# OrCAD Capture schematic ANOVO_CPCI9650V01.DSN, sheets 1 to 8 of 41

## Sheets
1 -COVER PAGE: title: 01--COVER PAGE; rev: 0.1; note: CPCI 965
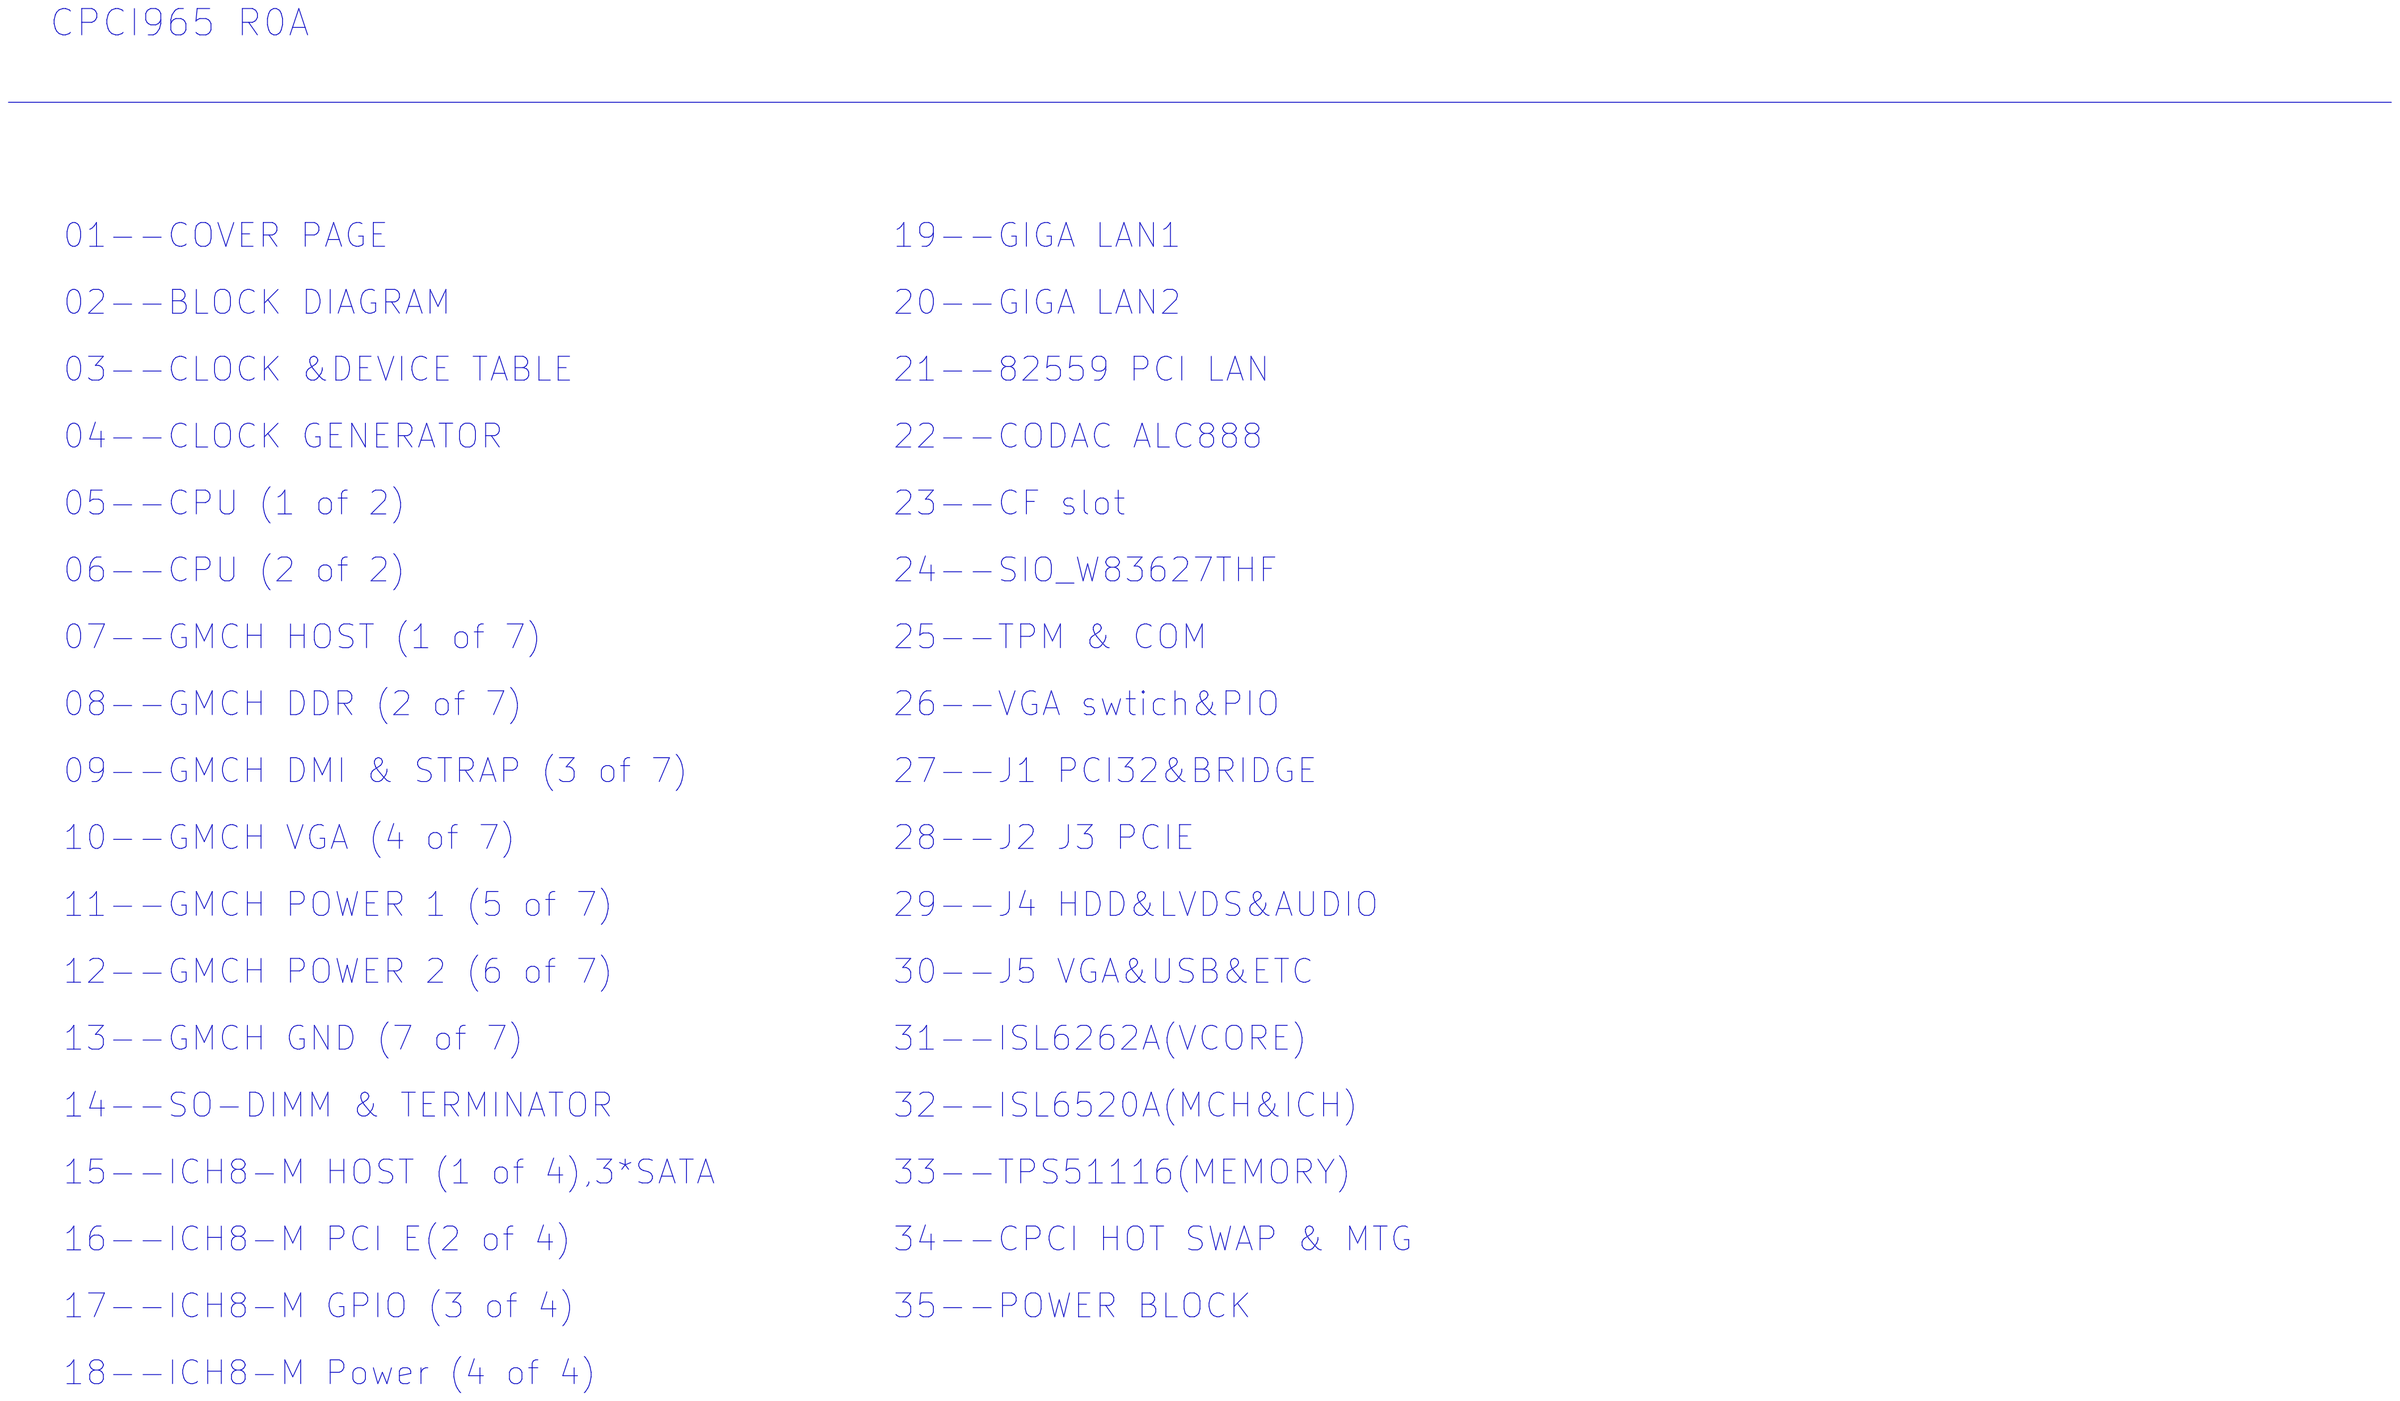
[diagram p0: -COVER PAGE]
2 -BLOCK DIAGRAM: title: 02--BLOCK DIAGRAM; note: CPCI965
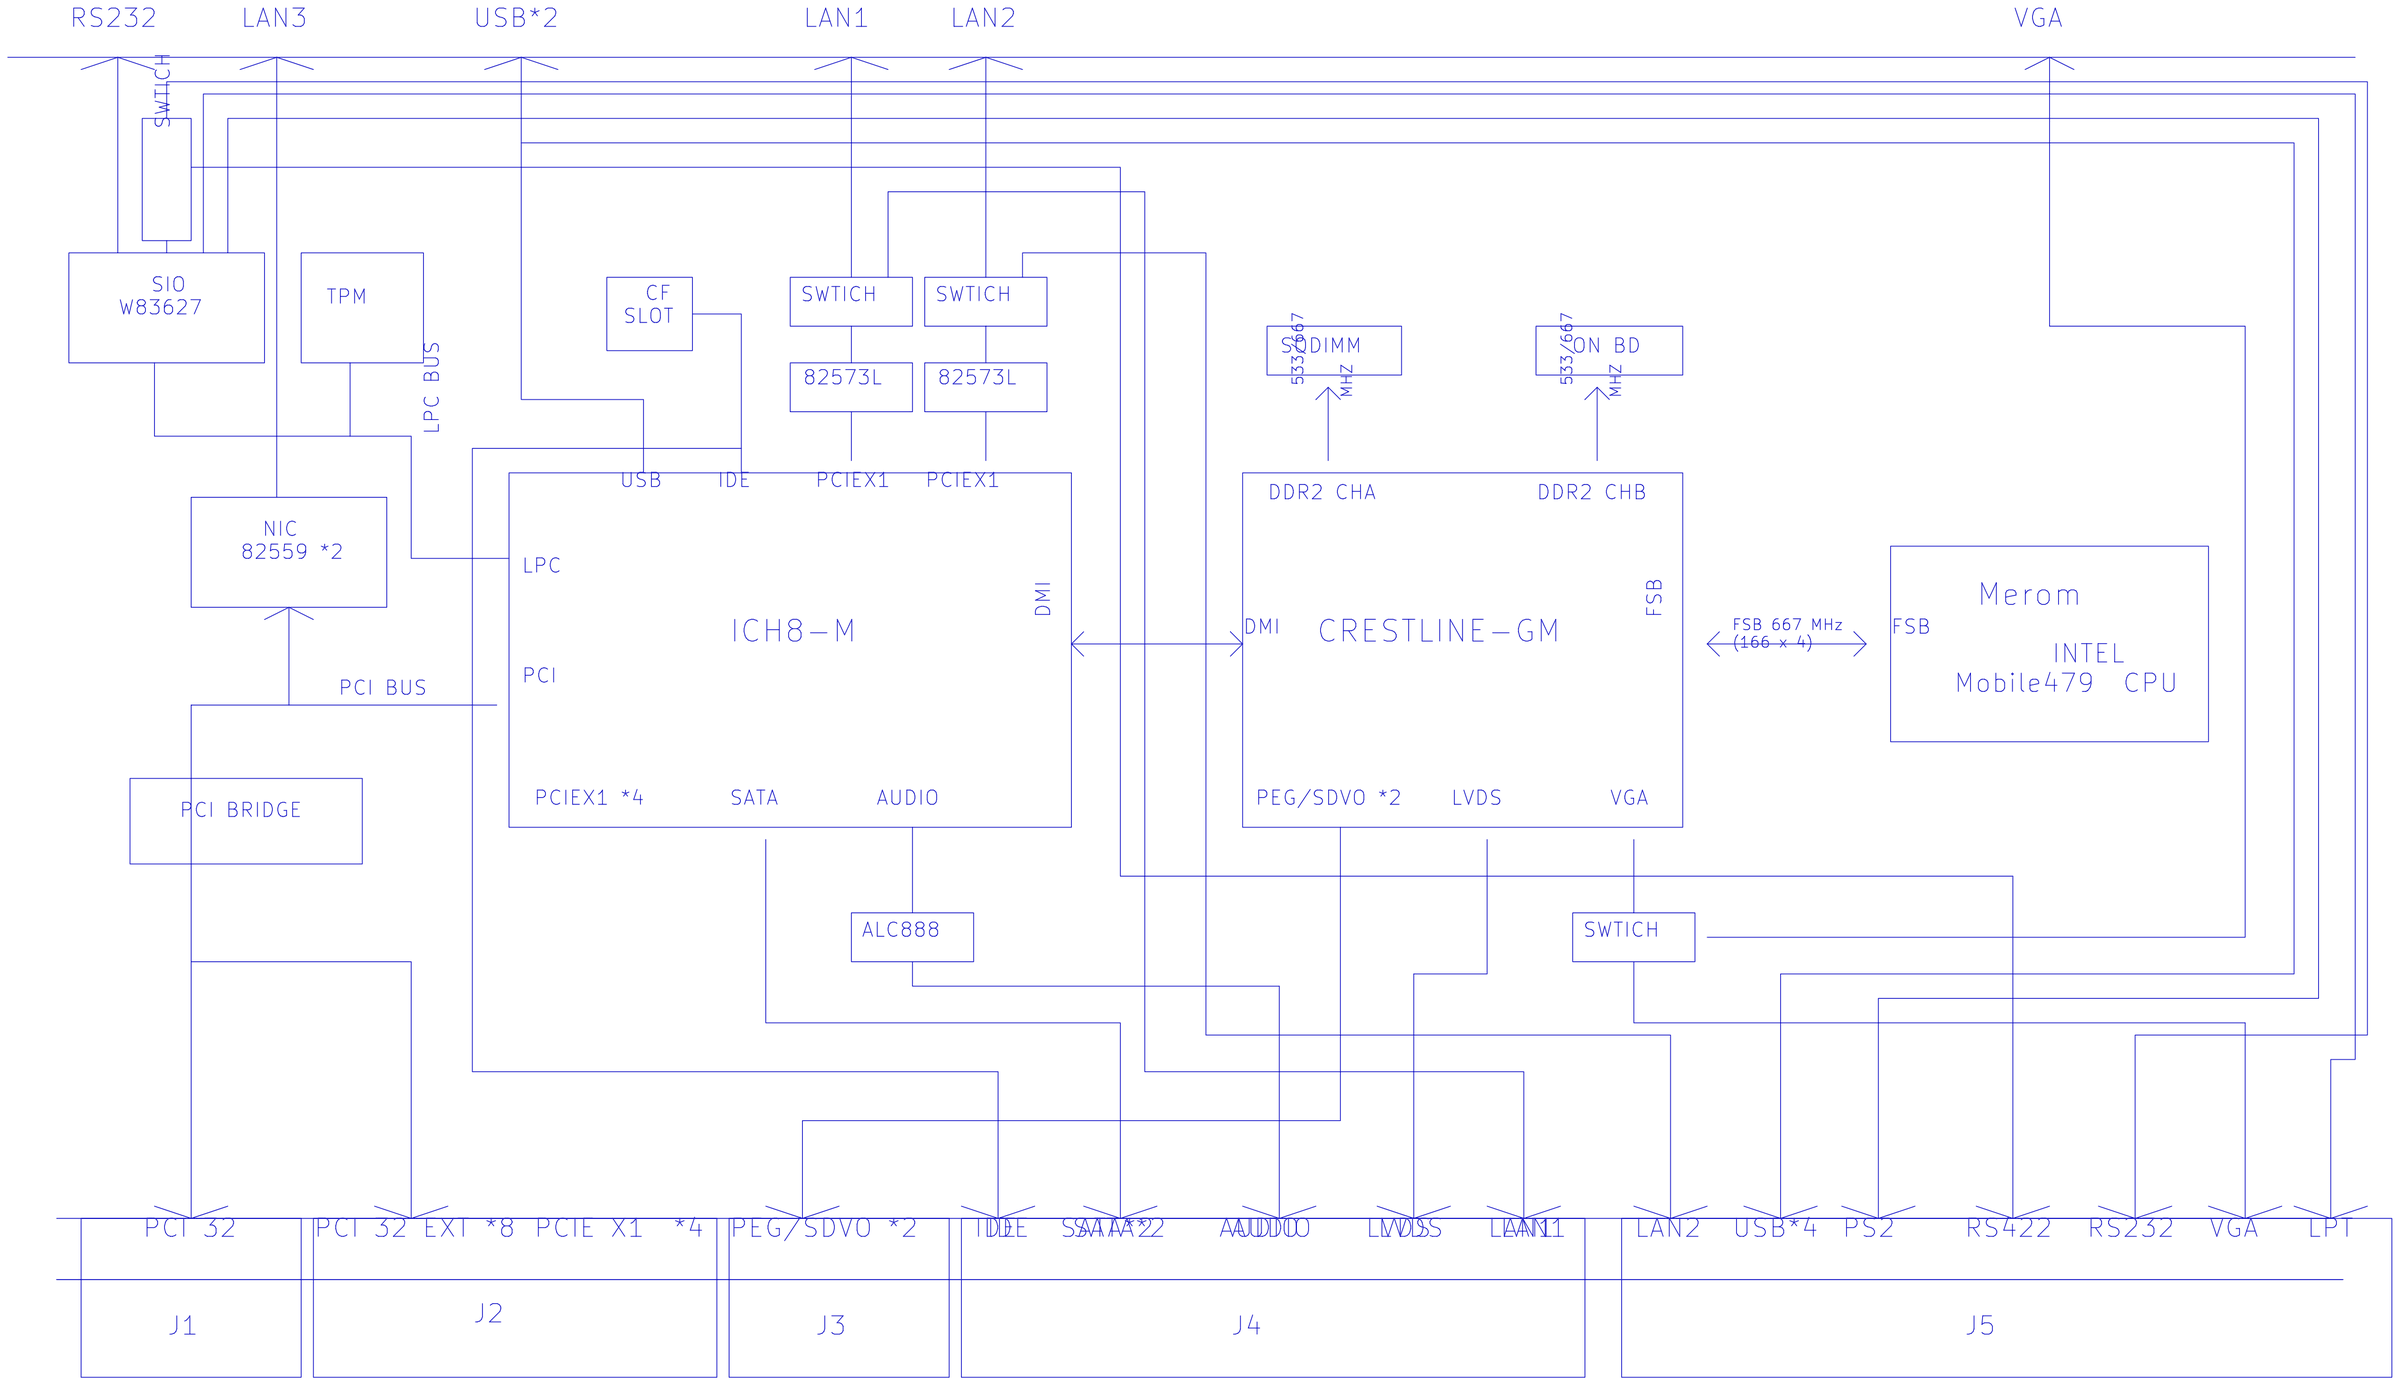
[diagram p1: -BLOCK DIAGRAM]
3 -CLOCK &DEVICE TABLE: title: 03--CLOCK &DEVICE TABLE
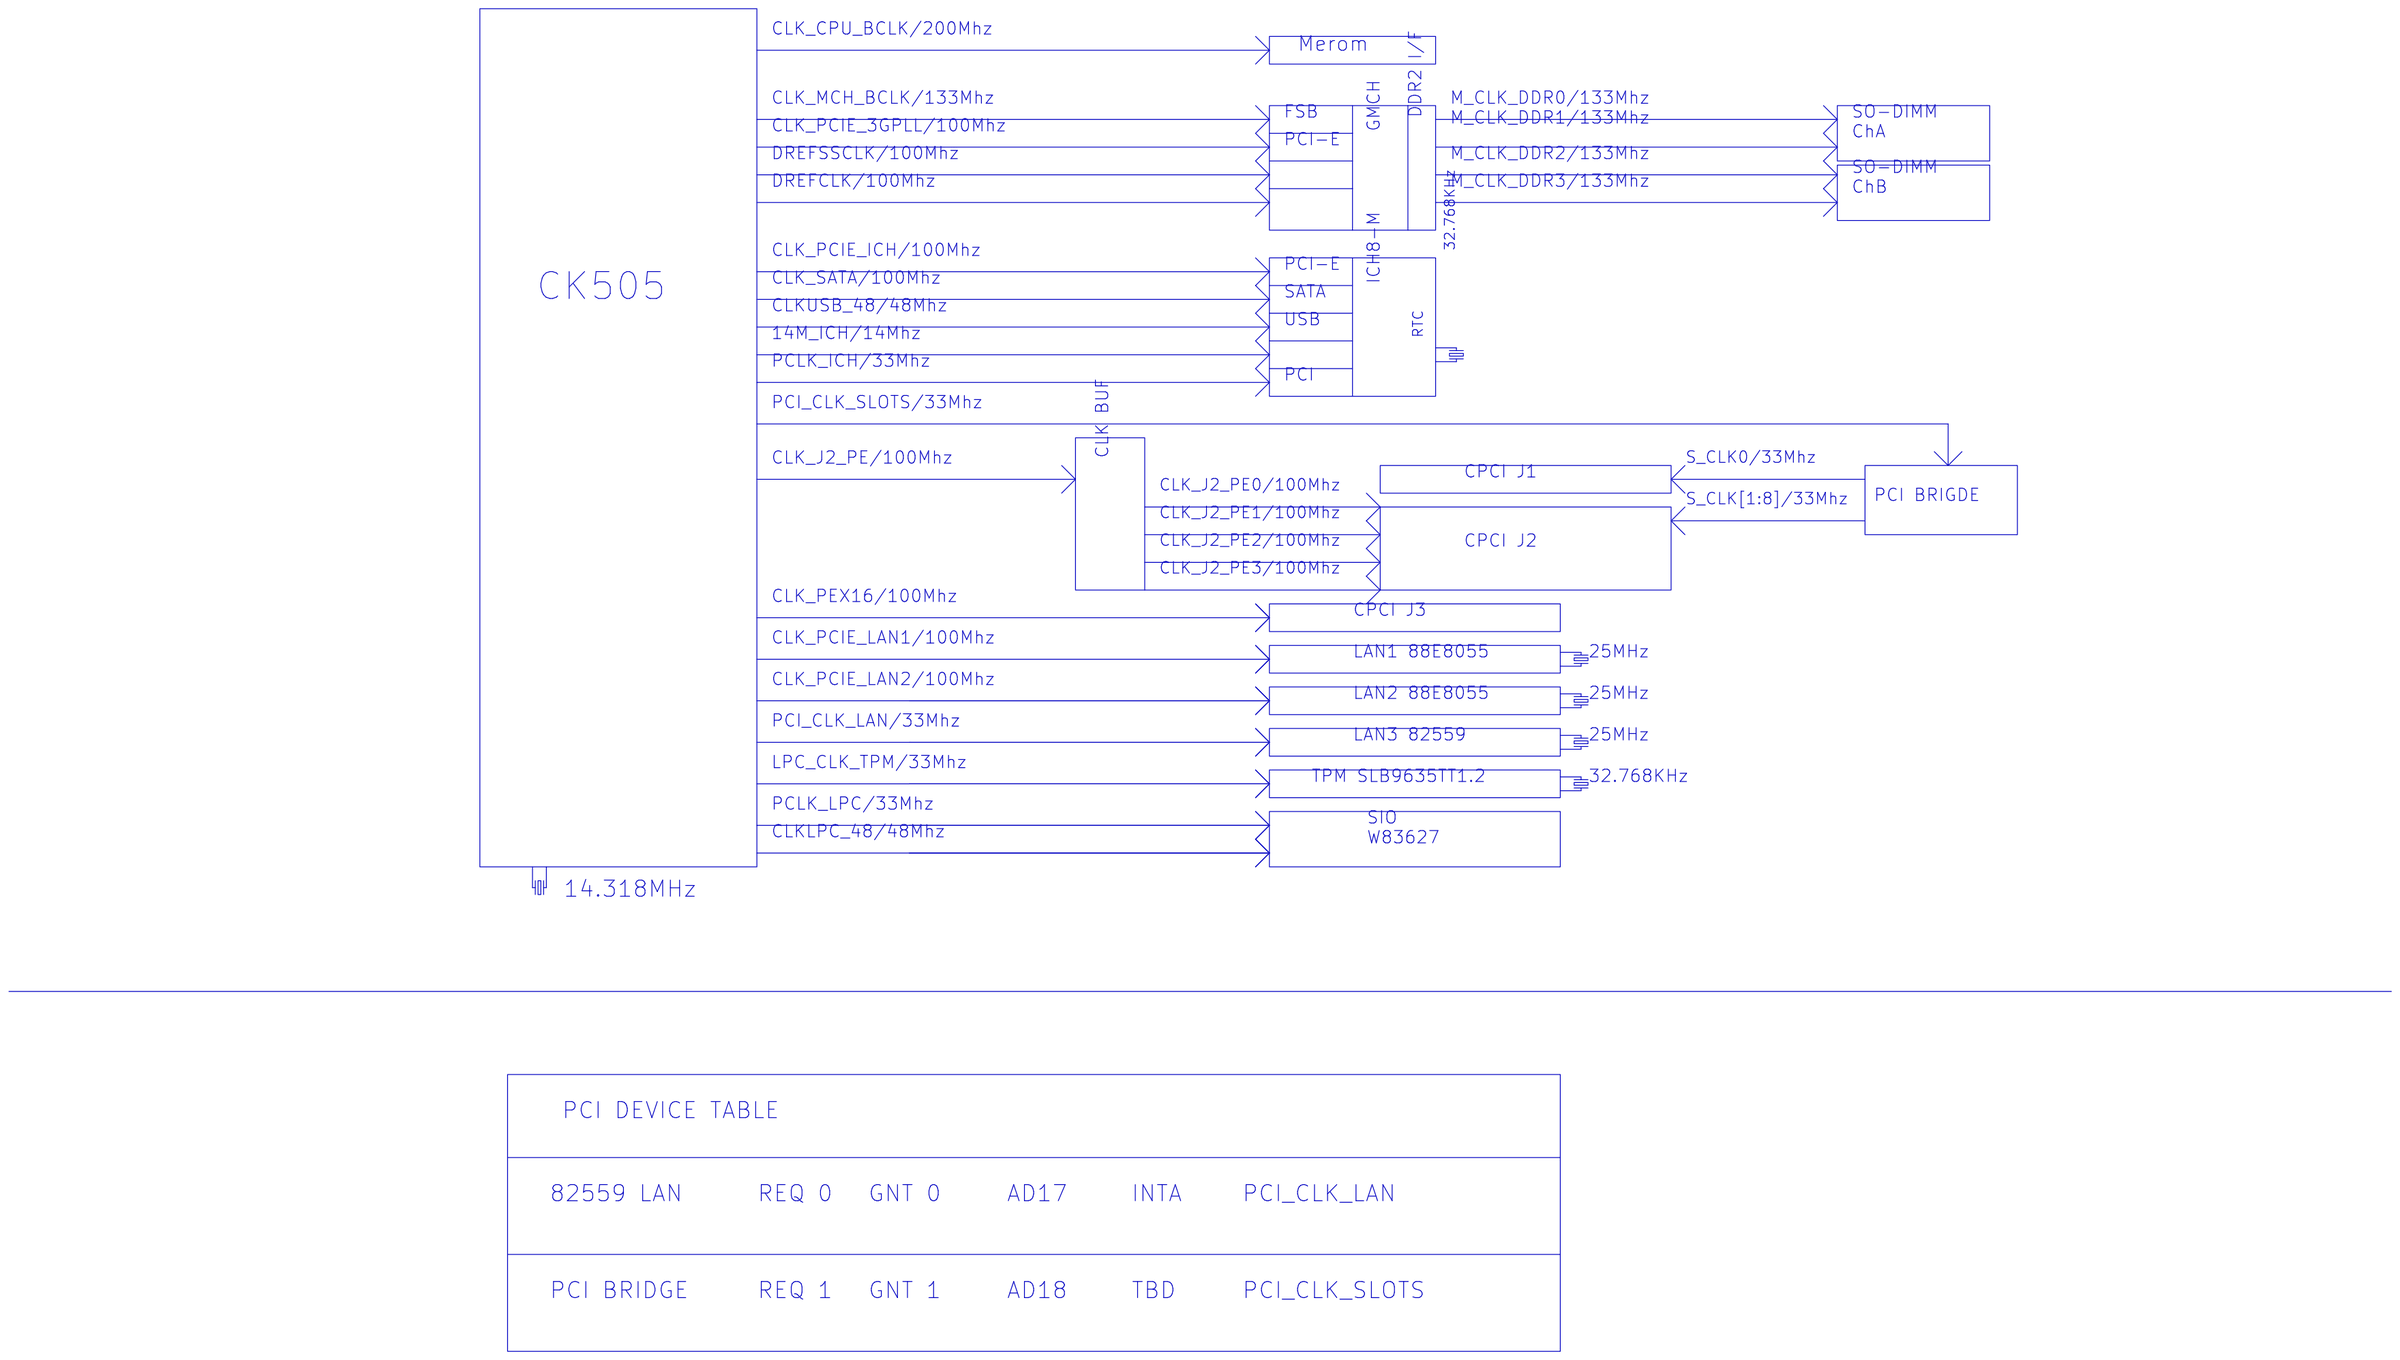
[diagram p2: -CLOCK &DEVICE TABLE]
4 -CLOCK GENERATOR: size C; title: 04--CLOCK GENERATOR
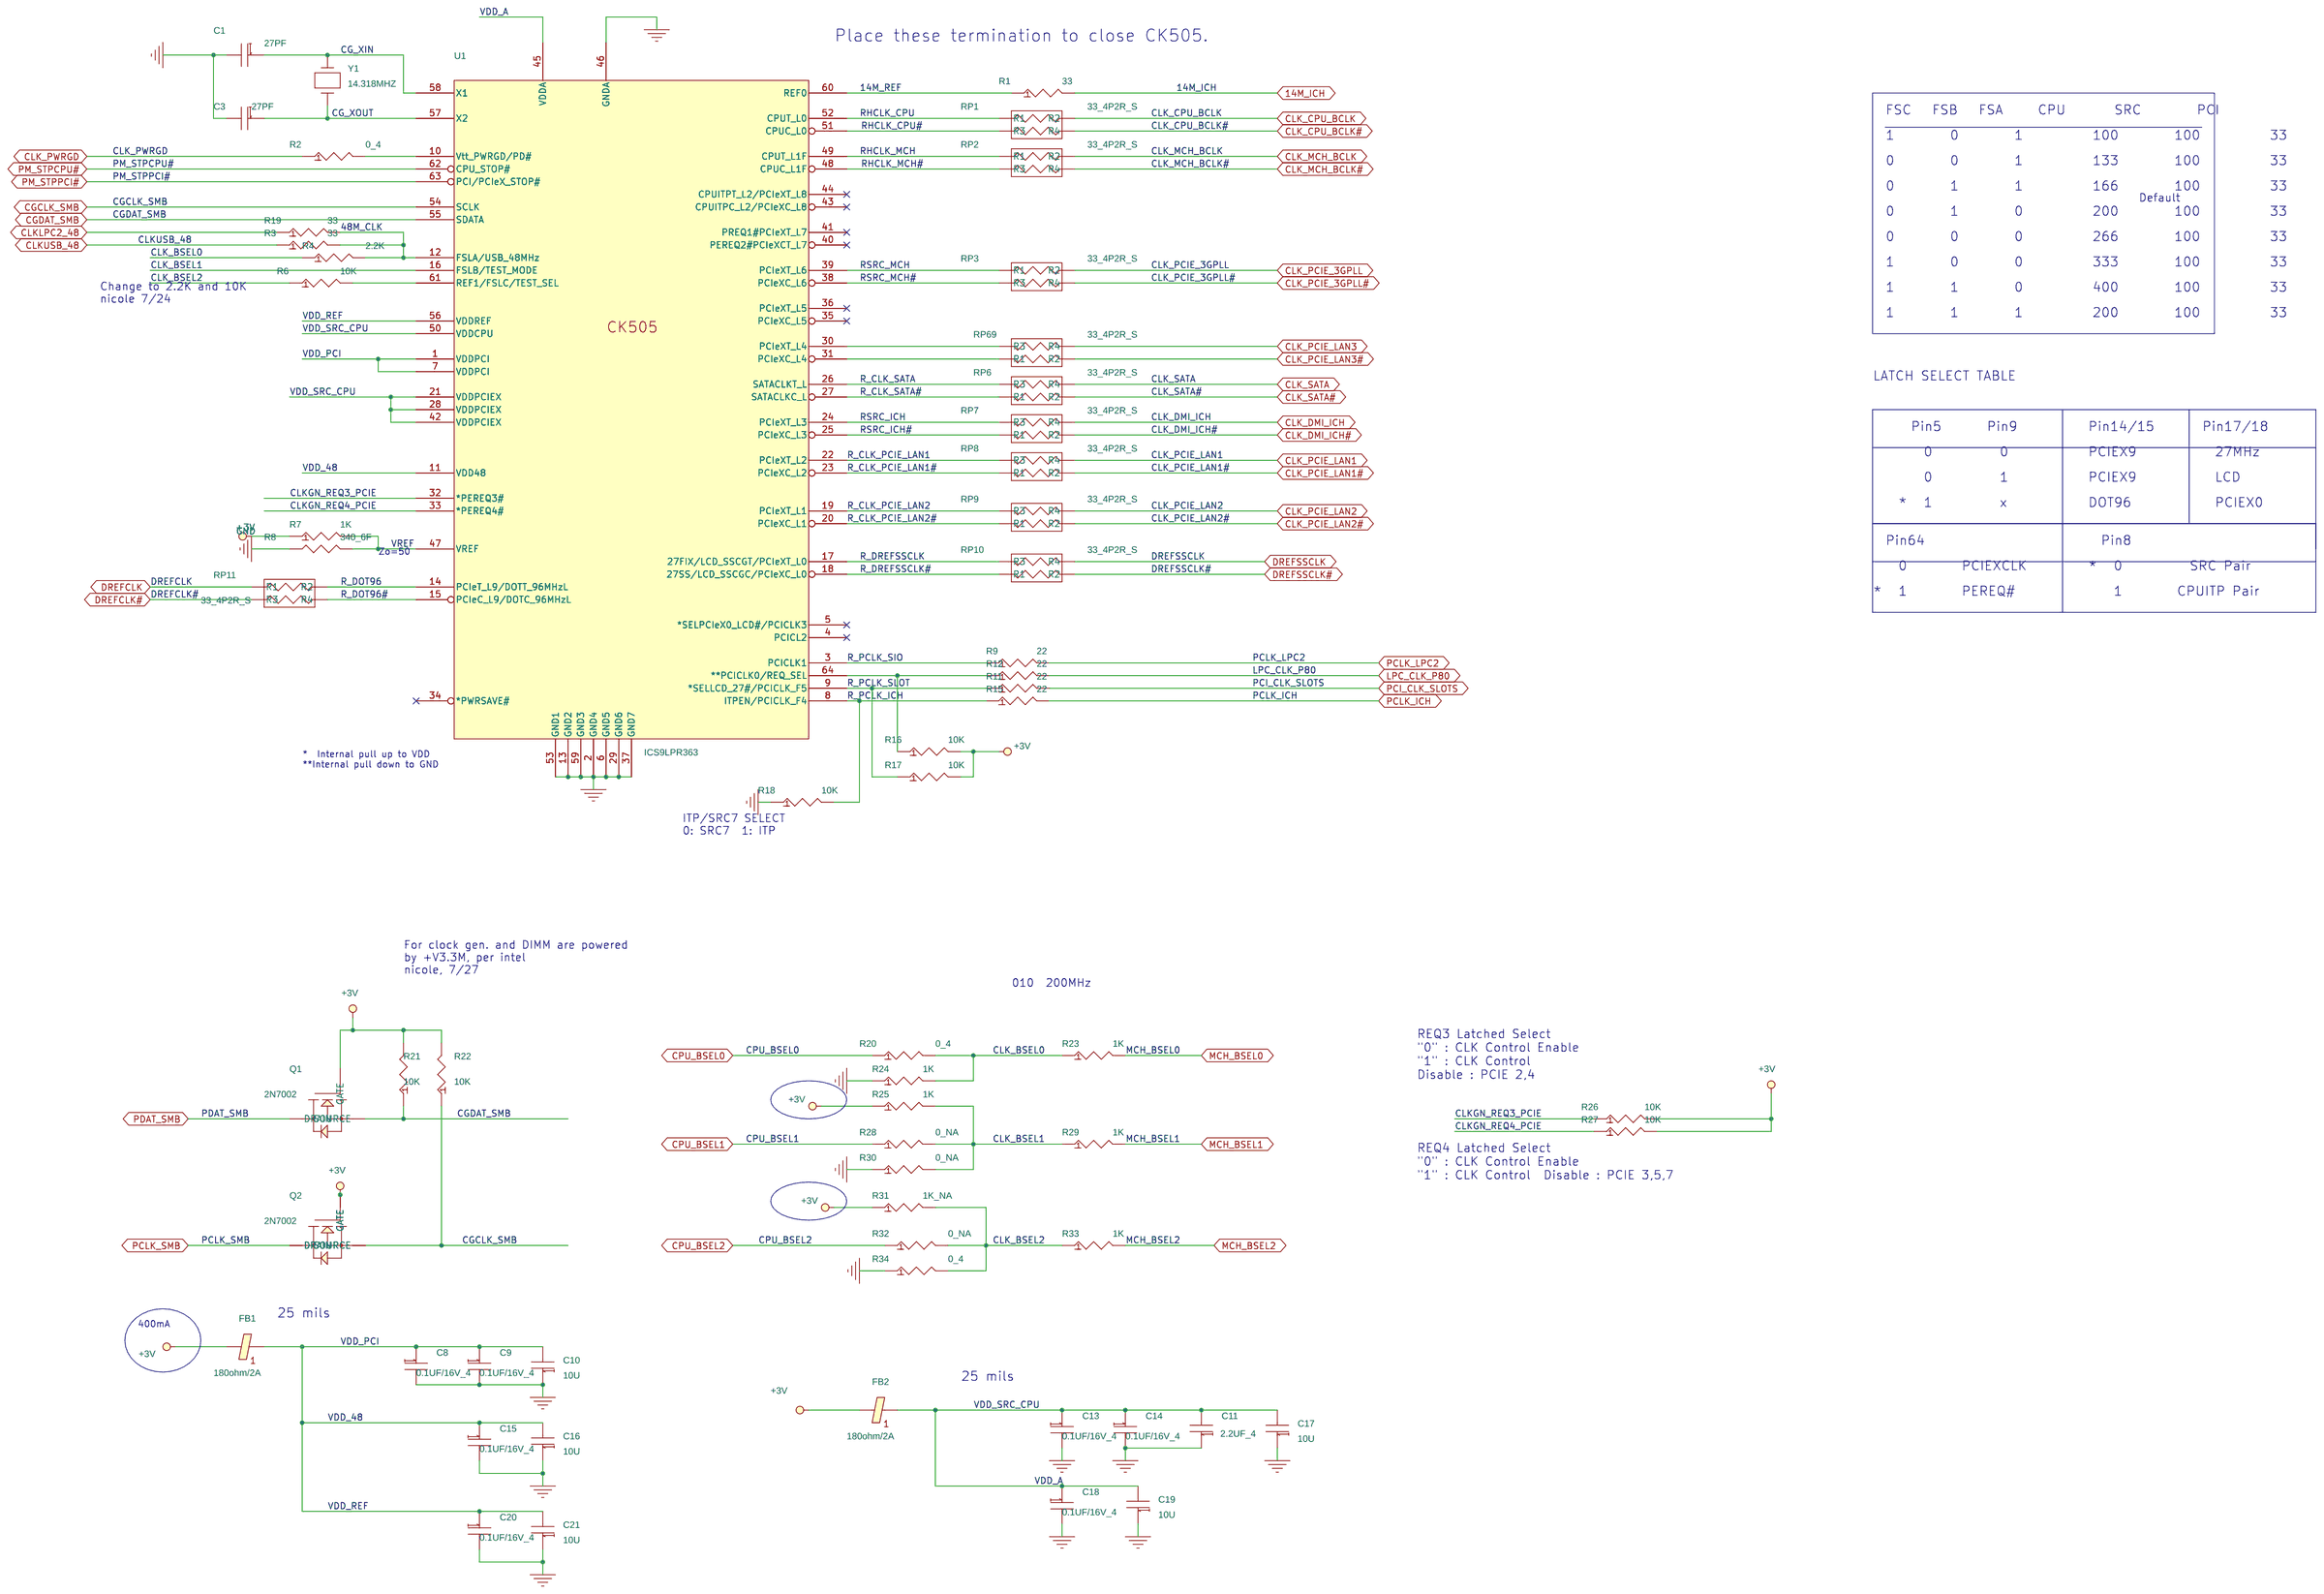
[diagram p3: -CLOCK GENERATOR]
5 -CPU (1 of 2): size C; title: 05--CPU (1 of 2)
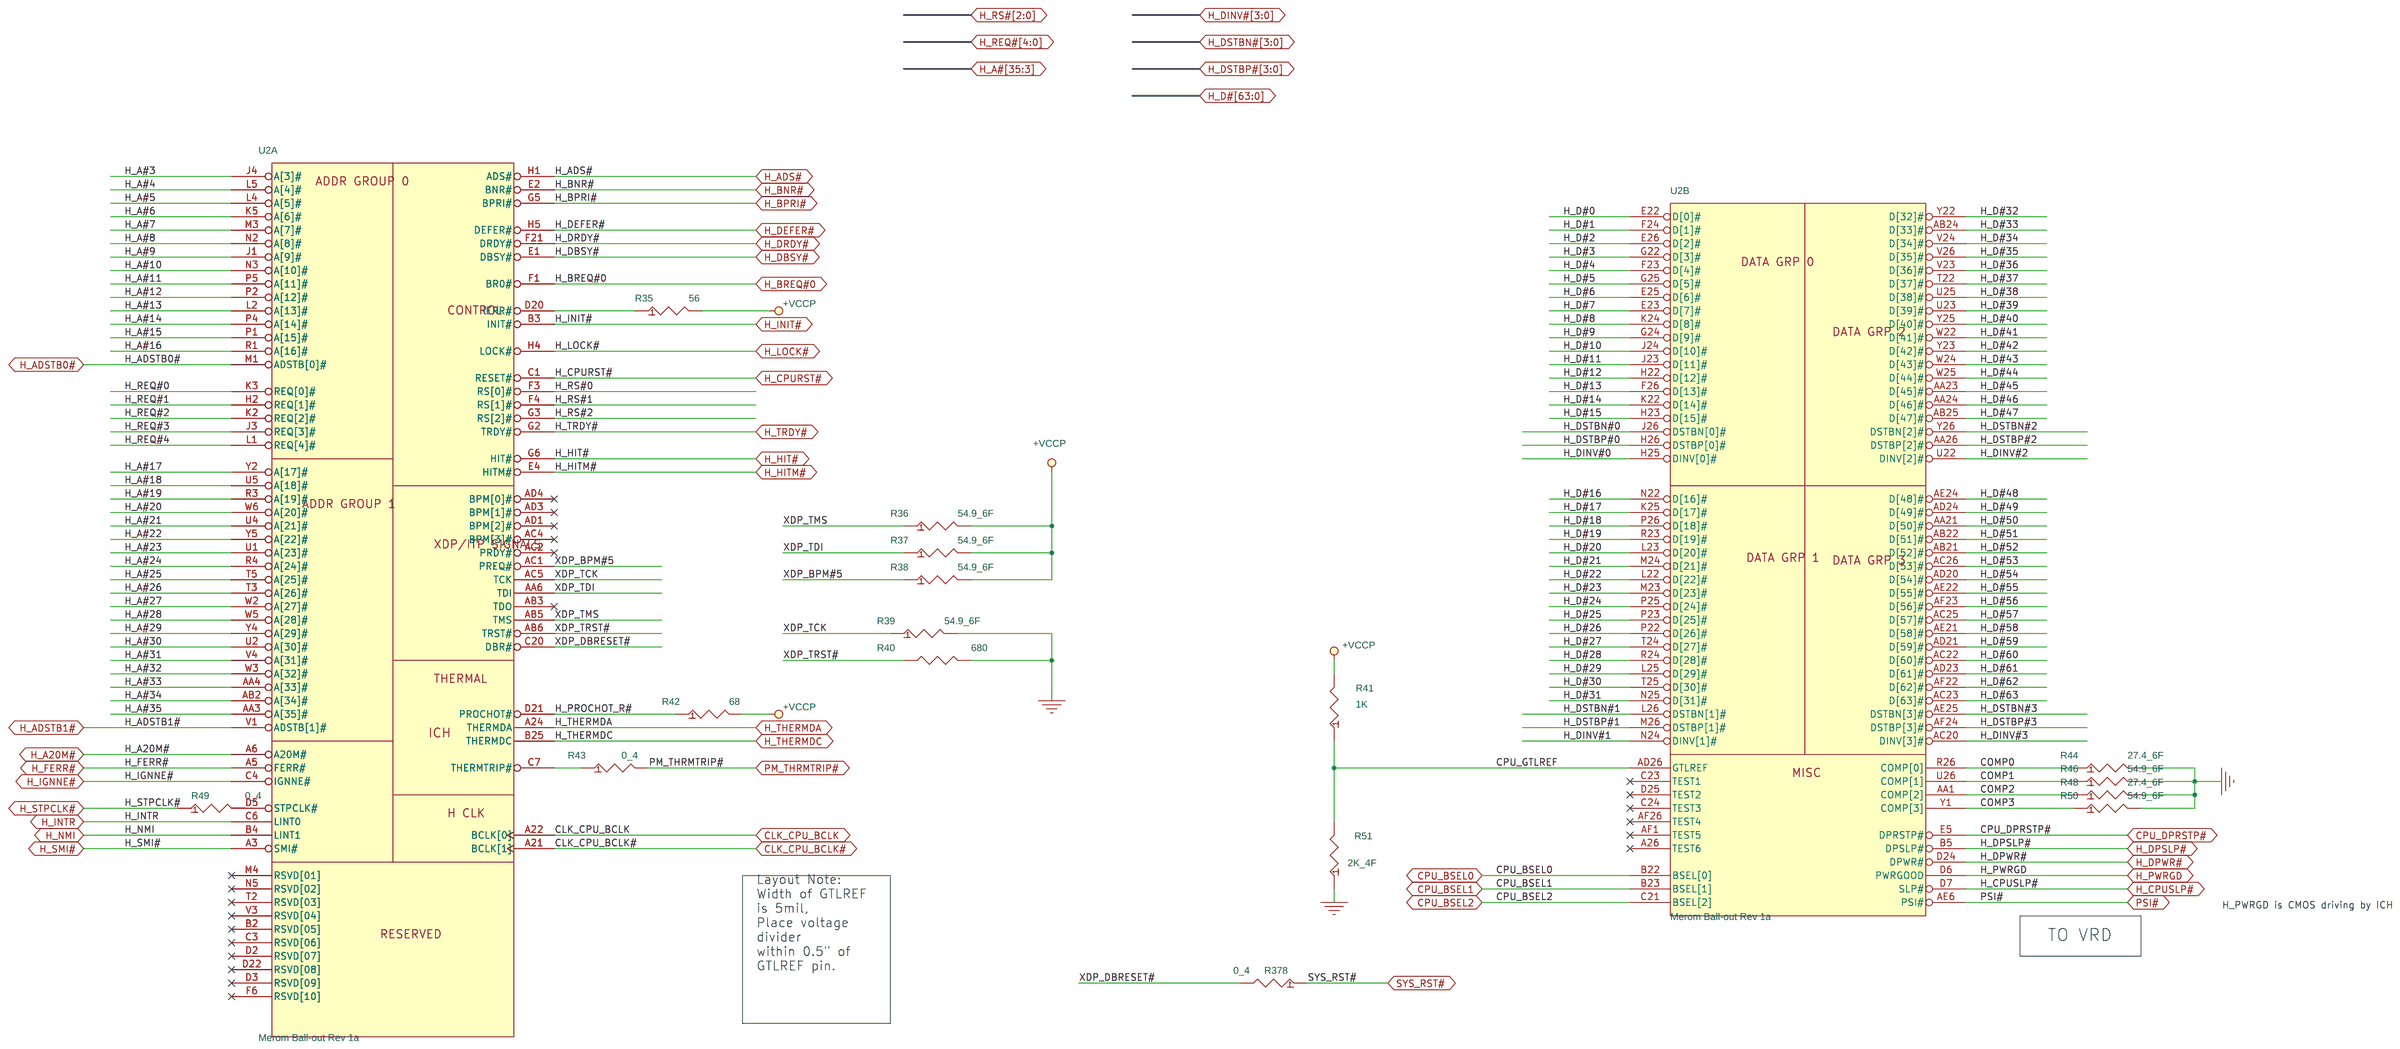
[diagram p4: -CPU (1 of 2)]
6 -CPU (2 of 2): size C; title: 06--CPU (2 of 2)
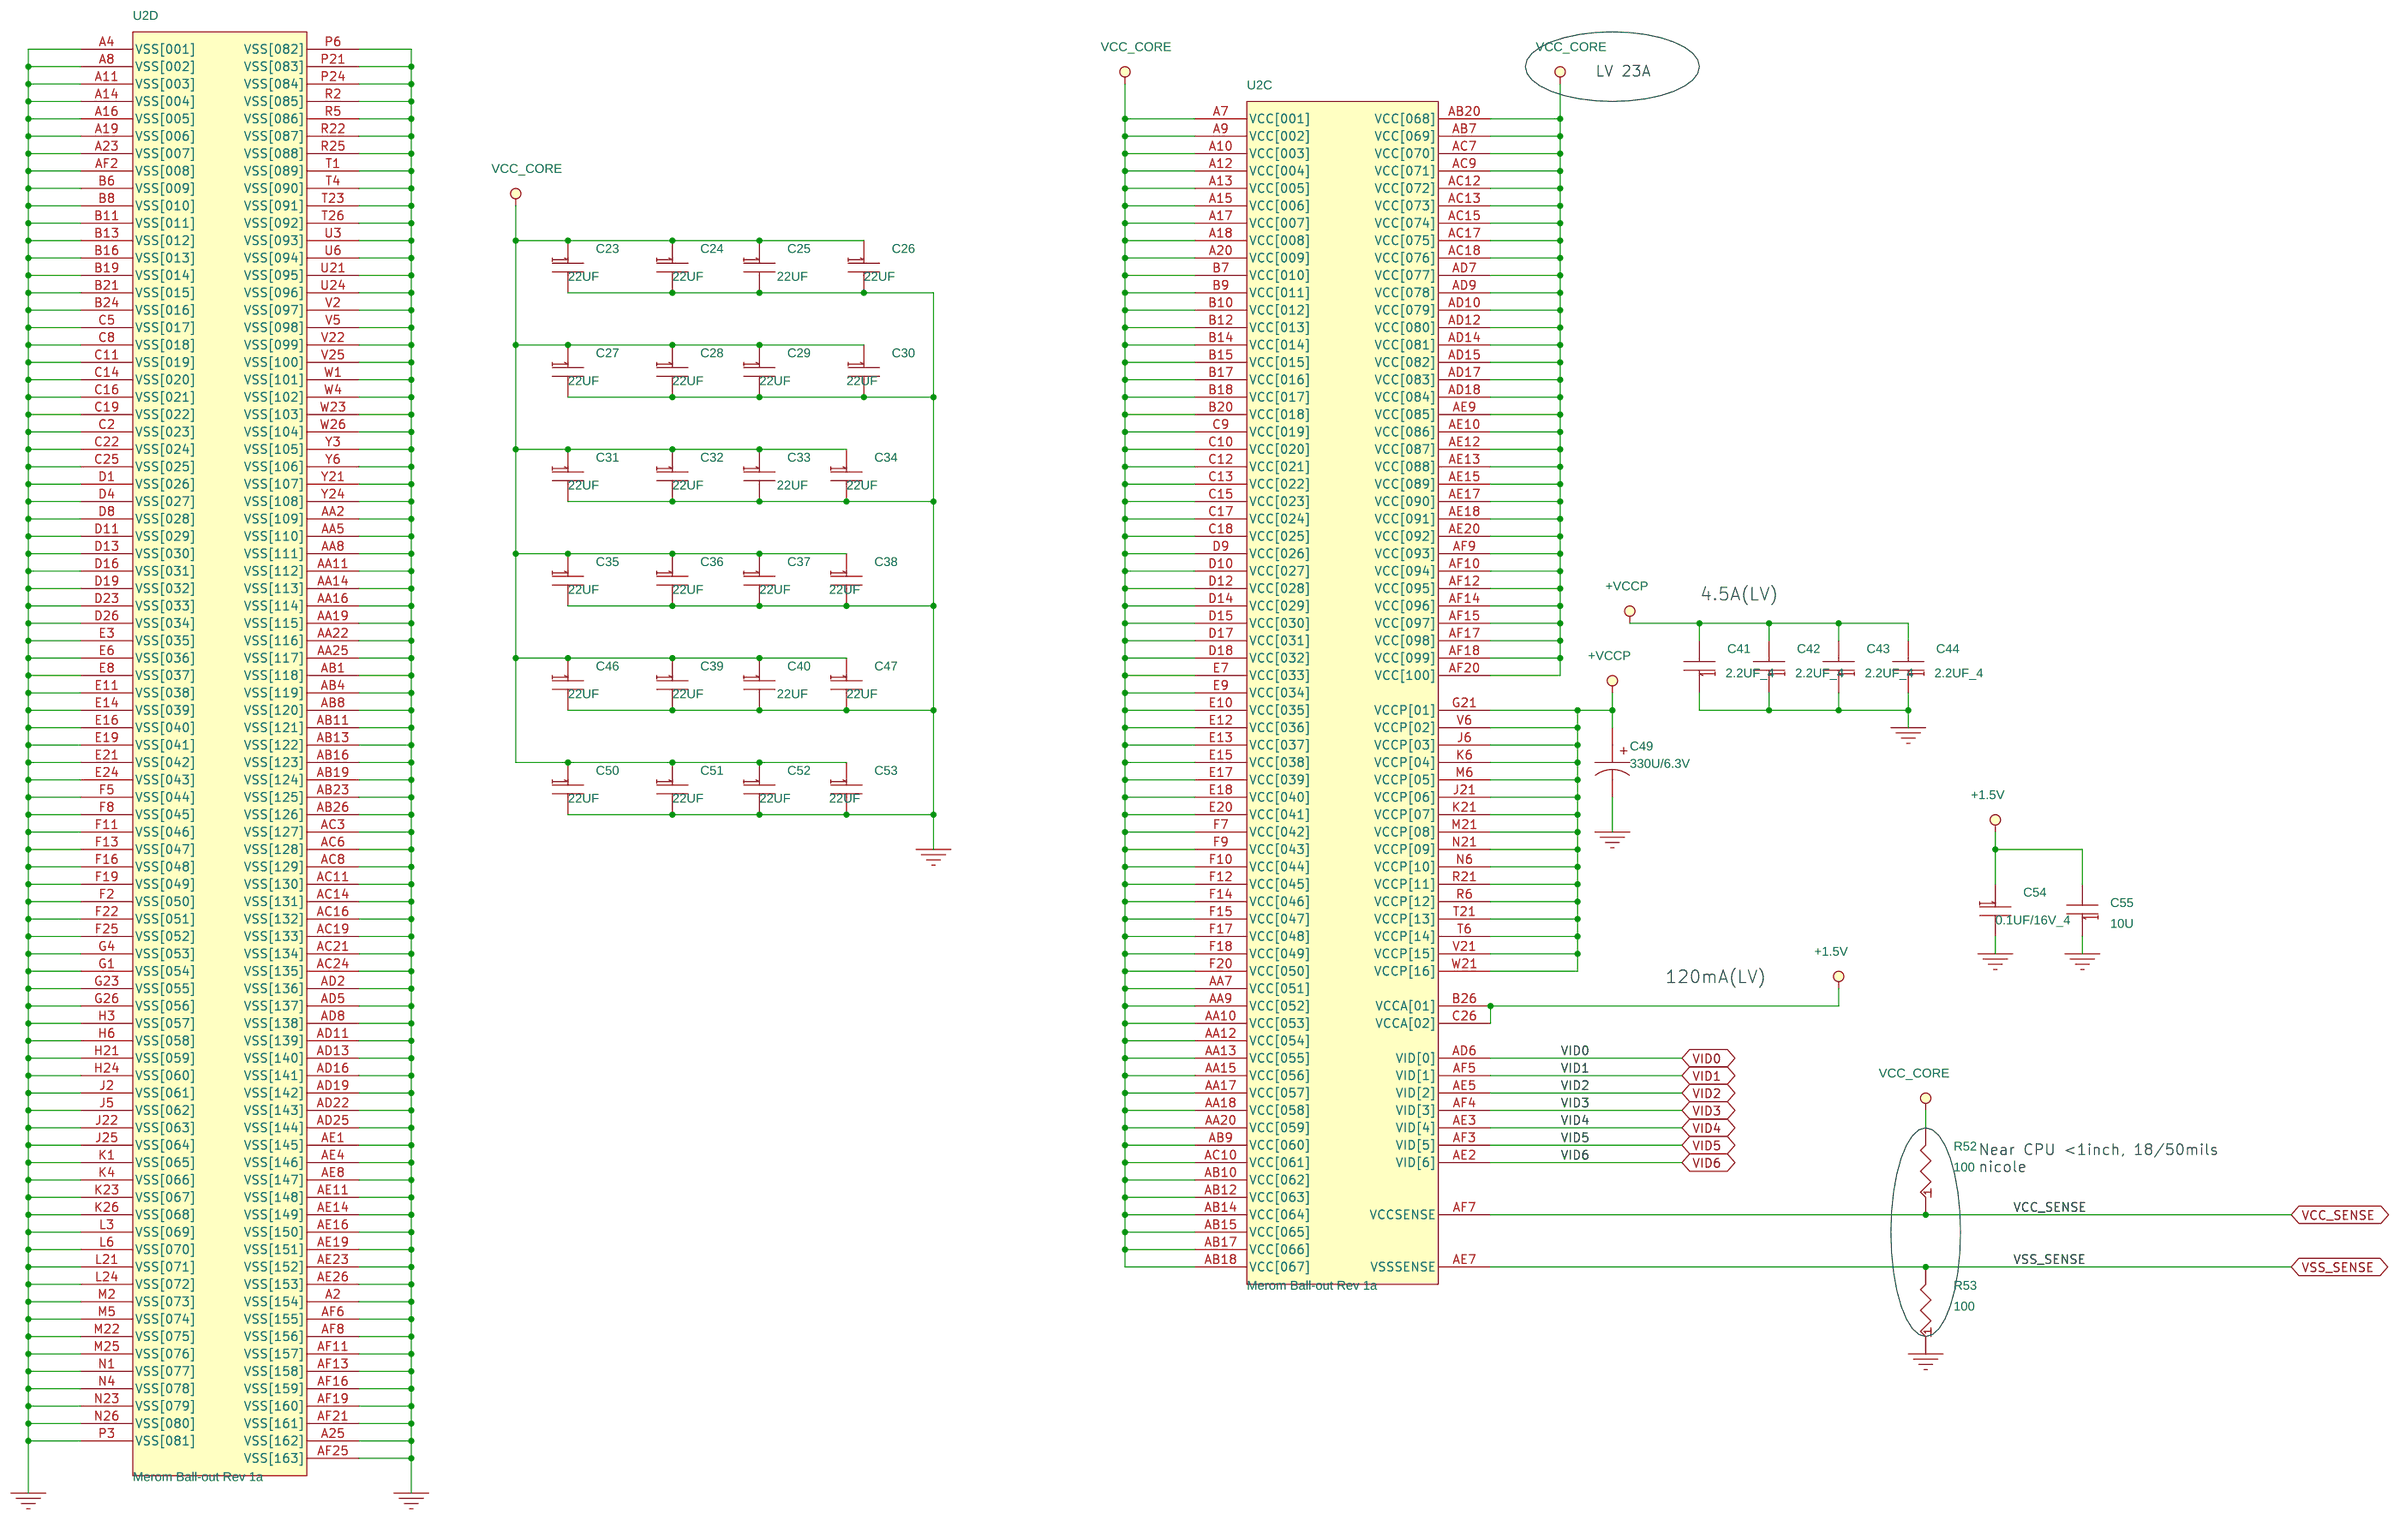
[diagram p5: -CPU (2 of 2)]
7 -GMCH HOST (1 of 7): size C; title: 07--GMCH HOST (1 of 7)
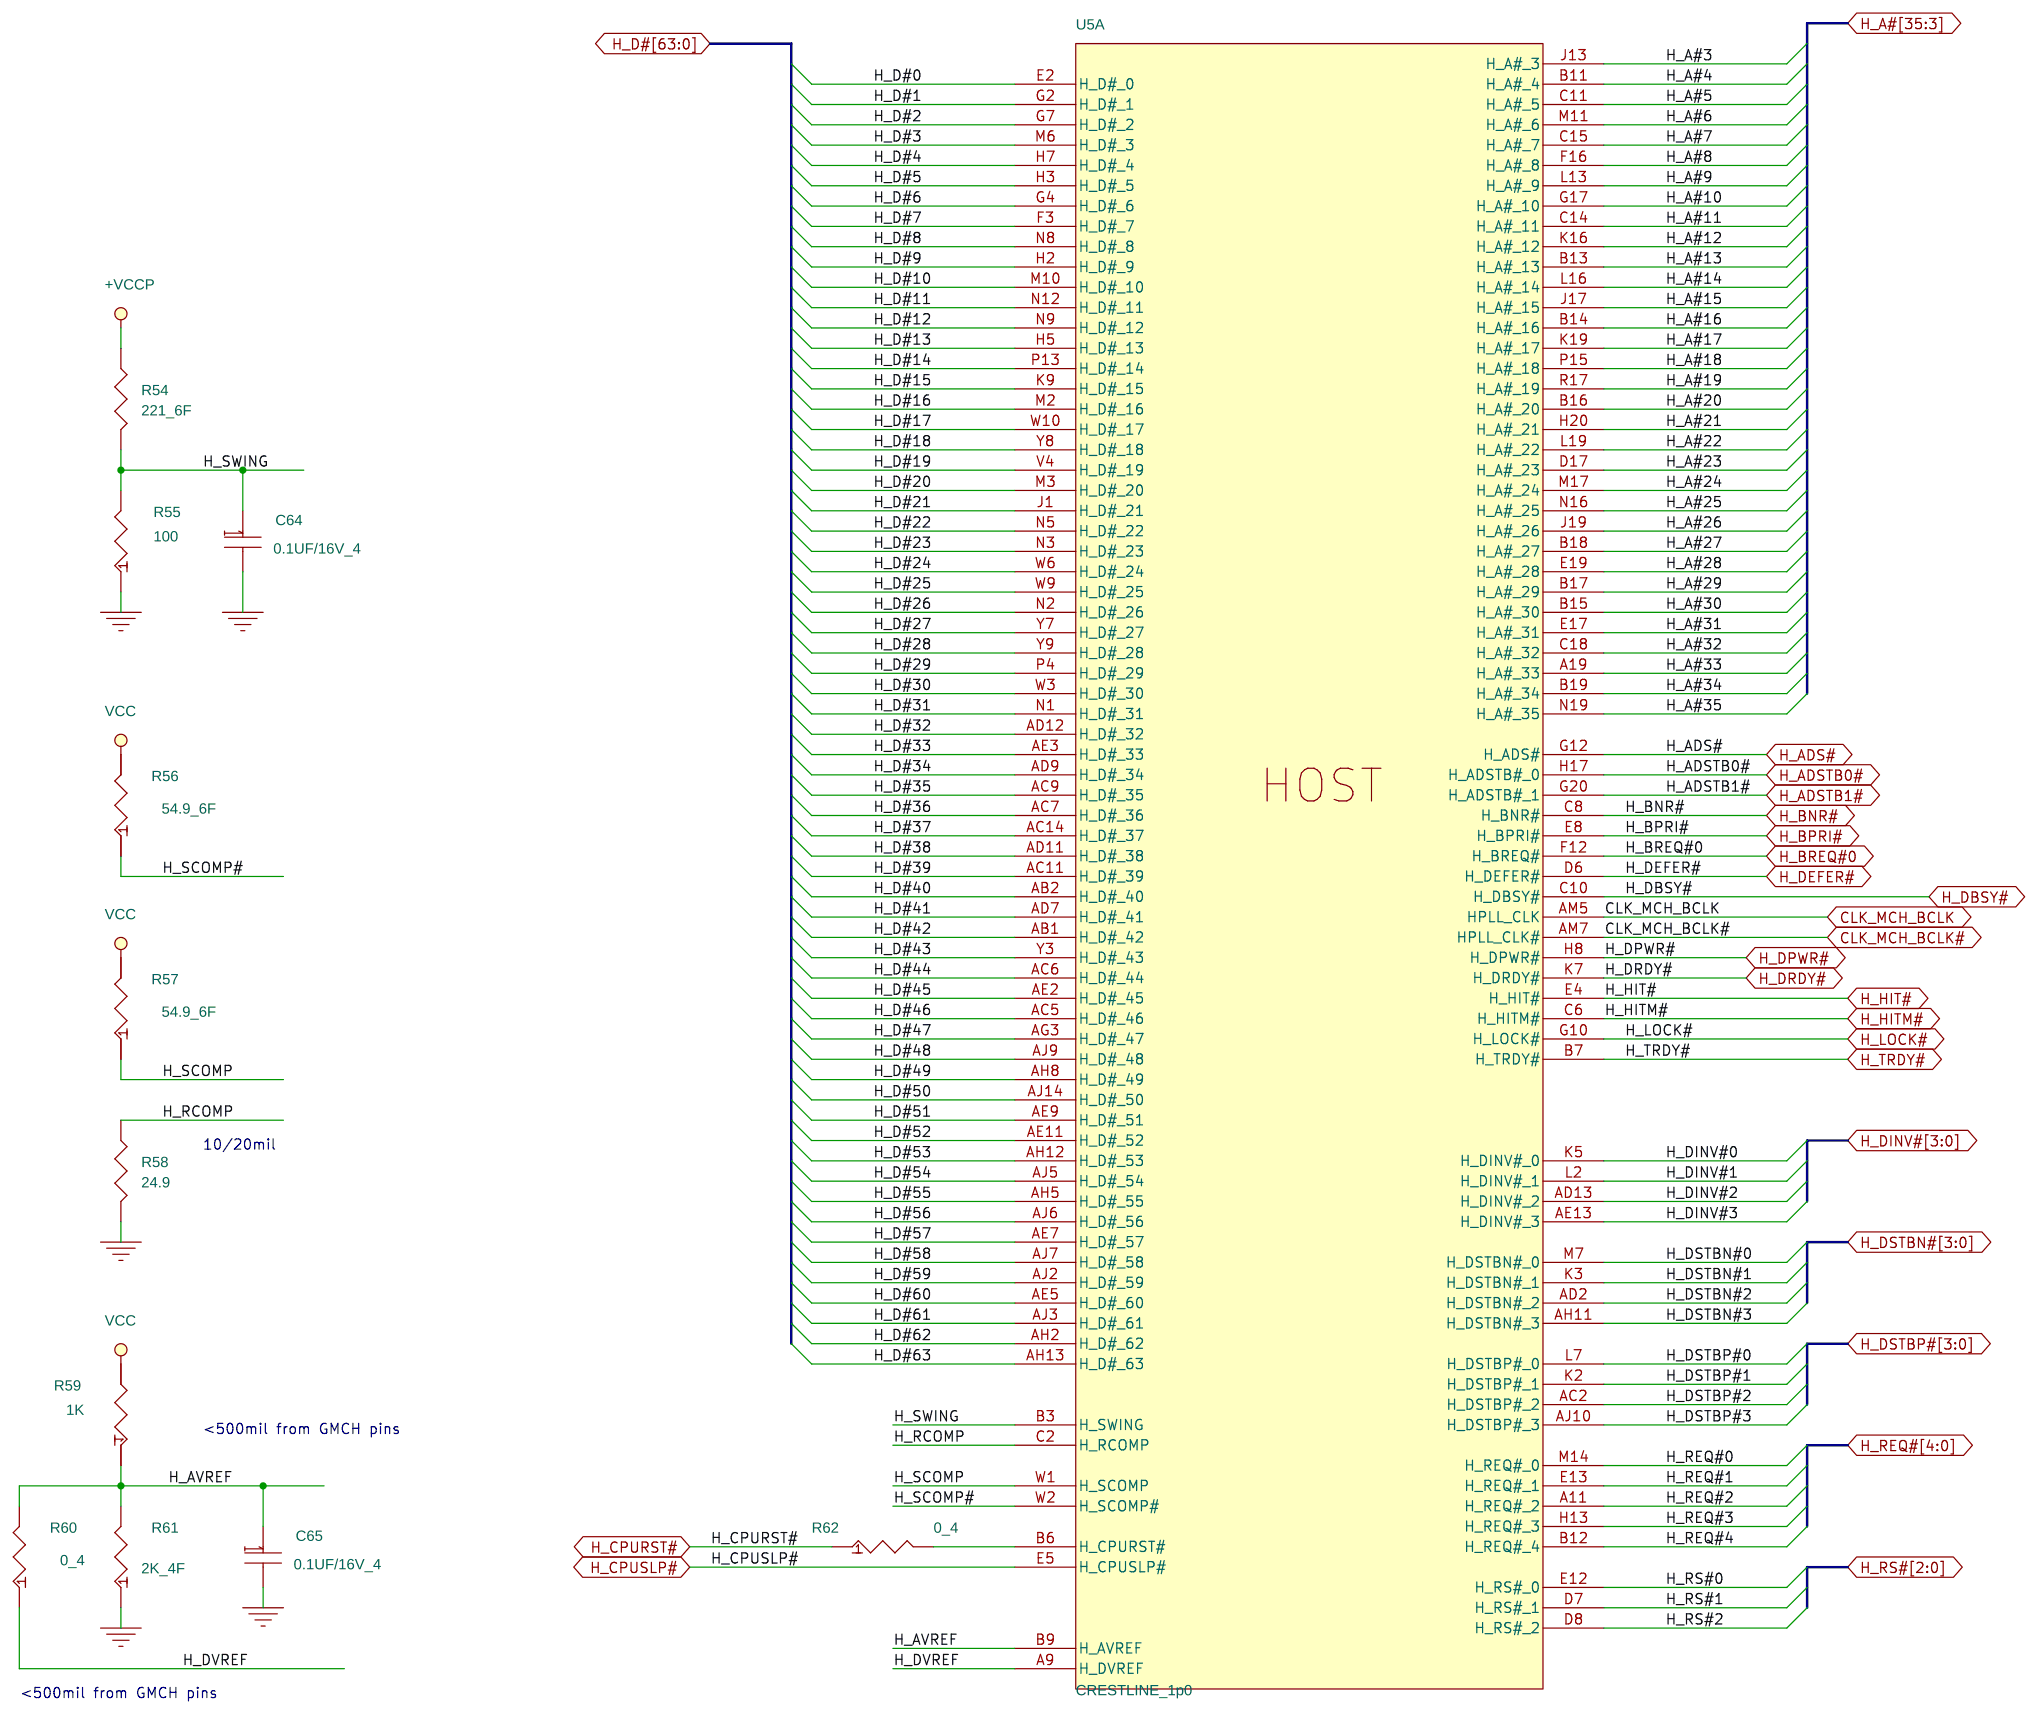
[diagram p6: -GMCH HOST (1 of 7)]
8 -GMCH DDR (2 of 7): size C; title: 08--GMCH DDR (2 of 7)
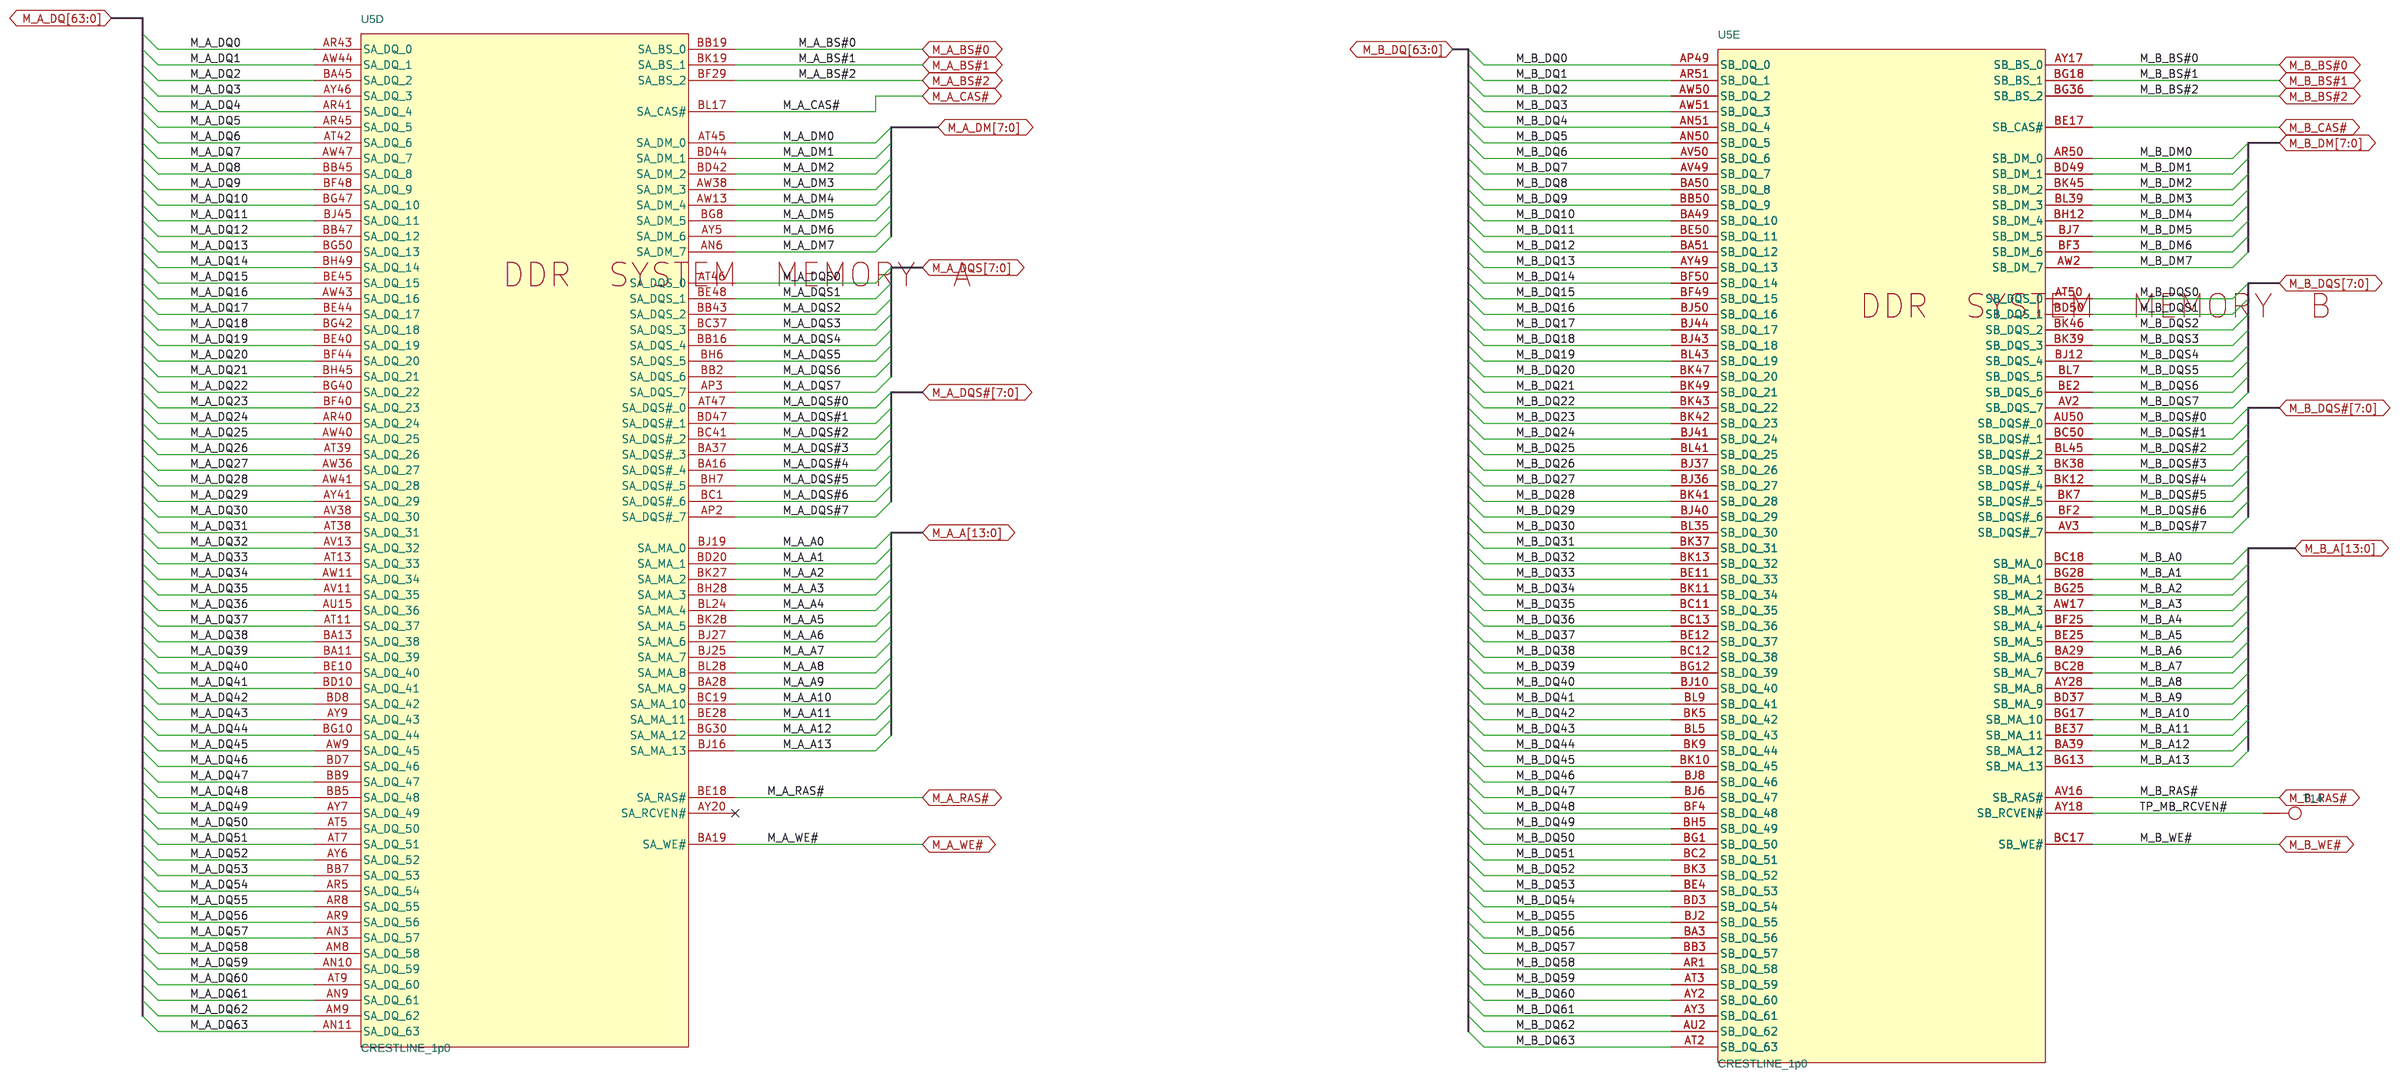
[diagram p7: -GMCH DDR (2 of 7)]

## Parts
sheet -CLOCK GENERATOR
C1  27PF  [0402D]
C3  27PF  [0402D]
C8  0.1UF/16V_4  [0402D]
C9  0.1UF/16V_4  [0402D]
C10  10U  [0805D]
C11  2.2UF_4  [0402D]
C13  0.1UF/16V_4  [0402D]
C14  0.1UF/16V_4  [0402D]
C15  0.1UF/16V_4  [0402D]
C16  10U  [0805D]
C17  10U  [0805D]
C18  0.1UF/16V_4  [0402D]
C19  10U  [0805D]
C20  0.1UF/16V_4  [0402D]
C21  10U  [0805D]
FB1  180ohm/2A  [0805D]
FB2  180ohm/2A  [0805D]
Q1  2N7002  [SOT23N_5]
Q2  2N7002  [SOT23N_5]
R1  33  [0402D]
R2  0_4  [0402D]
R3  33  [0402D]
R4  2.2K  [0603D]
R6  10K  [0402D]
R7  1K  [0402D]
R8  340_6F  [0603D]
R9  22  [0402D]
R11  22  [0402D]
R12  22  [0402D]
R15  22  [0402D]
R16  10K  [0402D]
R17  10K  [0402D]
R18  10K  [0402D]
R19  33  [0402D]
R20  0_4  [0402D]
R21  10K  [0402D]
R22  10K  [0402D]
R23  1K  [0402D]
R24  1K  [0402D]
R25  1K  [0402D]
R26  10K  [0402D]
R27  10K  [0402D]
R28  0_NA  [0402D]
R29  1K  [0402D]
R30  0_NA  [0402D]
R31  1K_NA  [0402D]
R32  0_NA  [0402D]
R33  1K  [0402D]
R34  0_4  [0402D]
RP1  33_4P2R_S  [4P2R-0404]
RP2  33_4P2R_S  [4P2R-0404]
RP3  33_4P2R_S  [4P2R-0404]
RP6  33_4P2R_S  [4P2R-0404]
RP7  33_4P2R_S  [4P2R-0404]
RP8  33_4P2R_S  [4P2R-0404]
RP9  33_4P2R_S  [4P2R-0404]
RP10  33_4P2R_S  [4P2R-0404]
RP11  33_4P2R_S  [4P2R-0404]
RP69  33_4P2R_S  [4P2R-0404]
U1  ICS9LPR363  [TSSOP64-8_1-5]
Y1  14.318MHZ  [FA-365]
sheet -CPU (1 of 2)
R35  56  [0402D]
R36  54.9_6F  [0603D]
R37  54.9_6F  [0603D]
R38  54.9_6F  [0603D]
R39  54.9_6F  [0603D]
R40  680  [0603D]
R41  1K  [0402D]
R42  68  [0603D]
R43  0_4  [0402D]
R44  27.4_6F  [0603D]
R46  54.9_6F  [0603D]
R48  27.4_6F  [0603D]
R49  0_4  [0402D]
R50  54.9_6F  [0603D]
R51  2K_4F  [0402D]
R378  0_4  [0402D]
U2  Merom Ball-out Rev 1a  [BGA479M-socket]  (sections A,B,C,D)
sheet -CPU (2 of 2)
C23  22UF  [0805D]
C24  22UF  [0805D]
C25  22UF  [0805D]
C26  22UF  [0805D]
C27  22UF  [0805D]
C28  22UF  [0805D]
C29  22UF  [0805D]
C30  22UF  [0805D]
C31  22UF  [0805D]
C32  22UF  [0805D]
C33  22UF  [0805D]
C34  22UF  [0805D]
C35  22UF  [0805D]
C36  22UF  [0805D]
C37  22UF  [0805D]
C38  22UF  [0805D]
C39  22UF  [0805D]
C40  22UF  [0805D]
C41  2.2UF_4  [0402D]
C42  2.2UF_4  [0402D]
C43  2.2UF_4  [0402D]
C44  2.2UF_4  [0402D]
C46  22UF  [0805D]
C47  22UF  [0805D]
C49  330U/6.3V  [1812A]
C50  22UF  [0805D]
C51  22UF  [0805D]
C52  22UF  [0805D]
C53  22UF  [0805D]
C54  0.1UF/16V_4  [0402D]
C55  10U  [0805D]
R52  100  [0402D]
R53  100  [0402D]
sheet -GMCH DDR (2 of 7)
T14  PAD  [pad-c3050]
sheet -GMCH HOST (1 of 7)
C64  0.1UF/16V_4  [0402D]
C65  0.1UF/16V_4  [0402D]
R54  221_6F  [0603D]
R55  100  [0402D]
R56  54.9_6F  [0603D]
R57  54.9_6F  [0603D]
R58  24.9  [0402D]
R59  1K  [0402D]
R60  0_4  [0402D]
R61  2K_4F  [0402D]
R62  0_4  [0402D]
sheet -GMCH POWER 2 (6 of 7)
U5  CRESTLINE_1p0  [fbga1299-intel-crestline]  (sections A,B,C,D,E,F,G,H,I,J)

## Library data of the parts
C1 C3 = CAP_NP: ANOVO DESCRIPTION: CAP;27P ,16V ,5% ,0402 ,NPO ,SMT; ANOVO PART NUMBER: 272043270101; BACKSIDE: 0; Part Type: CCAP; SMT: YES
C8 C9 C13-C15 C18 C20 C54 C64 C65 = CAP_NP: ANOVO DESCRIPTION: CAP;0.1U ,16V ,+80-20% ,0402 ,Y5V ,SMT; ANOVO PART NUMBER: 272043104401; BACKSIDE: 0; Part Type: CCAP; SMT: YES
C10 C16 C17 C19 C21 C55 = CAP_NP: ANOVO DESCRIPTION: CAP;10U,10V,+80-20%,0805,Y5V,SMT; ANOVO PART NUMBER: 272002106401; Part Type: CCAP
C11 C41-C44 = CAP_NP: ANOVO DESCRIPTION: CAP;2.2U ,6.3V ,10% ,0402 ,X7R ,SMT; ANOVO PART NUMBER: 272041225201
FB1 FB2 = FERRITE_BEAD: ANOVO DESCRIPTION: FERRITE CHIP;180 OHM/100MHZ,2A,0805,SMT; ANOVO PART NUMBER: 273001814300; BACKSIDE: 0; Part Type: FERRITE BEAD; SMT: YES
Q1 Q2 = MOSFET_N_3P: ANOVO DESCRIPTION: TRANS;2N7002,N-MOSFET,60V,500mA,SOT23; ANOVO PART NUMBER: 288227002001; BACKSIDE: 0; Part Type: MOSFET; SMT: YES
R1 R3 R19 = R_v2: ANOVO DESCRIPTION: RES;33 ,1/16W ,5% ,0402 ,SMT; ANOVO PART NUMBER: 271040330301; BACKSIDE: 0; Part Type: RESISTOR; SMT: YES
R2 R20 R28 R30 R32 R34 R43 R49 R60 R62 = R_v2: ANOVO DESCRIPTION: RES;0 ,1/16W ,5% ,0402 ,SMT; ANOVO PART NUMBER: 271040000301; BACKCOMP: YES; BACKSIDE: YES; ID: 0; Part Type: RESISTOR; SMT: YES
R4 = R_v2: ANOVO DESCRIPTION: RES;2.2K ,1/10W ,1% ,0603 ,SMT; ANOVO PART NUMBER: 271071222101; BACKSIDE: 0; Part Type: RESISTOR; SMT: YES
R6 R16-R18 R21 R22 R26 R27 = R_v2: ANOVO DESCRIPTION: RES;10K ,1/16W ,5% ,0402 ,SMT; ANOVO PART NUMBER: 271040103301; BACKSIDE: 0; Part Type: RESISTOR; SMT: YES
R7 R23-R25 R29 R33 R41 R59 = R_v2: ANOVO DESCRIPTION: RES;1K ,1/16W ,1% ,0402 ,SMT; ANOVO PART NUMBER: 271040102101; Part Type: RESISTOR
R8 = R_0: ANOVO DESCRIPTION: RES;340 ,1/10W ,1% ,0603 ,SMT; ANOVO PART NUMBER: 271071341101; Part Type: RESISTOR; Res: 348; SMT: YES; Tolerance: 1%; Watt: 1/10W
R9 R11 R12 R15 = R_v2: ANOVO DESCRIPTION: RES;22 ,1/16W ,5% ,0402 ,SMT; ANOVO PART NUMBER: 271040220301; POWER: 1/16W; Part Type: RESISTOR
R31 = R_v2: ANOVO DESCRIPTION: RES,1K   ,1/16W,5% ,0402,SMT; ANOVO PART NUMBER: 271071102401; BACKSIDE: 0; Part Type: RESISTOR; SMT: YES
RP1-RP3 RP6-RP11 RP69 = 4P2R-0404_2: 8ND PART FIELD: TOP; ANOVO DESCRIPTION: RES,33,1/16W,5%,0404,4P2R,SMT; ANOVO PART NUMBER: 271240330301; Function Code: CLK; Part Description: '  RES ARRAY CHIP 33 1/16W(5%,4P2R,0404)L-F  '; Part Number: CJ033042N11; Part_No: CJ033042N11
U1 = CK-505-ICS9LPR363_0: ANOVO DESCRIPTION: IC,ICS9LPR363,Clock Gen for Santa Rosa,TSSOP,64P,ICS; ANOVO PART NUMBER: 286509363001; Part Number: ALLPR363K08
Y1 = CRYSTAL_v2: 8ND PART FIELD: TOP; ANOVO DESCRIPTION: Xtal;14.318MHz,+-30ppm,20pF,5032,2p,SMT; ANOVO PART NUMBER: 274001435400; Function Code: CLK; Part Description: XTAL SMD 14.318MHZ(+-30PPM)6X14300042 LF; Part Number: BG614318081; Part_No: BG614318081
R35 = R_v2: ANOVO DESCRIPTION: RES,56 ,1/16W ,5%, 0402, SMT; ANOVO PART NUMBER: 271040560301; Part Type: RESISTOR
R36-R39 R46 R50 R56 R57 = R_v2: ANOVO DESCRIPTION: RES;54.9 ,1/10W ,1% ,0603 ,SMT; ANOVO PART NUMBER: 271071549811; BACKSIDE: 0; Part Type: RESISTOR; SMT: YES
R40 = R_22: 2ND PART FIELD: CS16802FB09; ANOVO DESCRIPTION: RES;680 ,1/10W ,5% ,0603 ,SMT; ANOVO PART NUMBER: 271071681301; BACKSIDE: 0; Function Code: CPU; Part Number: CS16802FB09; Part Type: RESISTOR; SMT: YES
R42 = R_v2: RES;68 ,1/10W ,1% ,0603 ,SMT; ANOVO DESCRIPTION: RES;68 ,1/10W ,1% ,0603 ,SMT; ANOVO PART NUMBER: 271071680101; BACKCOMP: YES; Part Type: RESISTOR; SMT: YES
R44 R48 = R_v2: ANOVO DESCRIPTION: RES,27.4 ,1/10W,1% ,0603,SMT; ANOVO PART NUMBER: 271071274811; BACKSIDE: 0; Part Type: RESISTOR; SMT: YES
R51 R61 = R_v2: ANOVO DESCRIPTION: RES;2K ,1/16W ,5% ,0402 ,SMT; ANOVO PART NUMBER: 271040202301; Part Type: RESISTOR
R378 = R_v2: ANOVO DESCRIPTION: RES;0 ,1/16W ,5% ,0402 ,SMT; ANOVO PART NUMBER: 271040000301; POWER: 1/16w; Part Type: RESISTOR
U2 = IC,Merom,9-5,Ball-outRev1a
C23-C40 C46 C47 C50-C53 = CAP_NP: ANOVO DESCRIPTION: CAP,22U ,CR,16V ,+80-20%,0805,Y5V,SMT,TAIYO; ANOVO PART NUMBER: 272003226401; BACKSIDE: 0; Part Type: CCAP; SMT: YES
C49 = CAPACITOR_POL: ANOVO DESCRIPTION: TANCAP,330U,6.3V,20%,D size, SMT; ANOVO PART NUMBER: 272633371011; Part Number: CH7331M8834
R52 R53 R55 = R_v2: ANOVO DESCRIPTION: RES;100 ,1/16W ,1% ,0402 ,SMT; ANOVO PART NUMBER: 271040101101; Part Type: RESISTOR
T14 = PAD_1: 8ND PART FIELD: BOT; Function Code: CLG; Part Number: *
R54 = R_0: ANOVO DESCRIPTION: RES;221 ,1/10W ,1% ,0603 ,SMT; ANOVO PART NUMBER: 271071221011; BACKSIDE: 0; Part Number: CS12212FB19; Part Type: RESISTOR; Res: 221; SMT: YES; Tolerance: 1%; Watt: 1/16W
R58 = R_0: ANOVO DESCRIPTION: RES;24.9 ,1/16W ,1% ,0402 ,SMT; ANOVO PART NUMBER: 271040249811; Function Code: CLG; POWER: 1/16W; Part Number: CS02492FB29; Part Type: RESISTOR; Size: 0402; Tolerance: 1%; Watt: 1/16W
U5 = TMP_160502: ANOVO DESCRIPTION: IC,LE82GME965,GMCH,FBGA,1299B,Intel; ANOVO PART NUMBER: 284508296501; NO_STUFF: .; Part Number: AJ0QK860T13

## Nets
+1.5V: C54.1 C55.2 U2.B26(VCCA[01]) U2.C26(VCCA[02]) ; also on sheet 12 16 18 32 33
+3V: FB1.2 FB2.2 Q1.1(GATE) Q2.1(GATE) R7.1 R16.2 R17.2 R21.2 R22.2 R25.1 R26.2 R27.2 R31.1 ; also on sheet 9 10 12 15 16 17 18 19 20 21 22 23 24 25 26 27 28 31 32 34 35 41
+VCCP: C41.2 C42.2 C43.2 C44.2 C49.1 R35.2 R36.2 R37.2 R38.2 R41.2 R42.2 R54.1 R56.2 R57.2 R59.2 U2.G21(VCCP[01]) U2.J6(VCCP[03]) U2.J21(VCCP[06]) U2.K6(VCCP[04]) U2.K21(VCCP[07]) U2.M6(VCCP[05]) U2.M21(VCCP[08]) U2.N6(VCCP[10]) U2.N21(VCCP[09]) U2.R6(VCCP[12]) U2.R21(VCCP[11]) U2.T6(VCCP[14]) U2.T21(VCCP[13]) U2.V6(VCCP[02]) U2.V21(VCCP[15]) U2.W21(VCCP[16]) ; also on sheet 10 11 12 15 18 21 31 32
GND: C1.2 C3.2 C8.2 C9.2 C10.1 C11.1 C13.2 C14.2 C15.2 C16.1 C17.1 C18.2 C19.1 C20.2 C21.1 C23.2 C24.2 C25.2 C26.2 C27.2 C28.2 C29.2 C30.2 C31.2 C32.2 C33.2 C34.2 C35.2 C36.2 C37.2 C38.2 C39.2 C40.2 C41.1 C42.1 C43.1 C44.1 C46.2 C47.2 C49.2 C50.2 C51.2 C52.2 C53.2 C54.2 C55.1 C64.2 C65.2 R8.1 R18.1 R24.1 R30.1 R34.1 R39.2 R40.2 R44.2 R46.2 R48.2 R50.2 R51.1 R53.1 R55.1 R58.2 R61.1 U1.2(GND4) U1.6(GND5) U1.13(GND2) U1.29(GND6) U1.37(GND7) U1.46(GNDA) U1.53(GND1) U1.59(GND3) U2.A2(VSS[154]) U2.A4(VSS[001]) U2.A8(VSS[002]) U2.A11(VSS[003]) U2.A14(VSS[004]) U2.A16(VSS[005]) U2.A19(VSS[006]) U2.A23(VSS[007]) U2.A25(VSS[162]) U2.AA2(VSS[109]) U2.AA5(VSS[110]) U2.AA8(VSS[111]) U2.AA11(VSS[112]) U2.AA14(VSS[113]) U2.AA16(VSS[114]) U2.AA19(VSS[115]) U2.AA22(VSS[116]) U2.AA25(VSS[117]) U2.AB1(VSS[118]) U2.AB4(VSS[119]) U2.AB8(VSS[120]) U2.AB11(VSS[121]) U2.AB13(VSS[122]) U2.AB16(VSS[123]) U2.AB19(VSS[124]) U2.AB23(VSS[125]) U2.AB26(VSS[126]) U2.AC3(VSS[127]) U2.AC6(VSS[128]) U2.AC8(VSS[129]) U2.AC11(VSS[130]) U2.AC14(VSS[131]) U2.AC16(VSS[132]) U2.AC19(VSS[133]) U2.AC21(VSS[134]) U2.AC24(VSS[135]) U2.AD2(VSS[136]) U2.AD5(VSS[137]) U2.AD8(VSS[138]) U2.AD11(VSS[139]) U2.AD13(VSS[140]) U2.AD16(VSS[141]) U2.AD19(VSS[142]) U2.AD22(VSS[143]) U2.AD25(VSS[144]) U2.AE1(VSS[145]) U2.AE4(VSS[146]) U2.AE8(VSS[147]) U2.AE11(VSS[148]) U2.AE14(VSS[149]) U2.AE16(VSS[150]) U2.AE19(VSS[151]) U2.AE23(VSS[152]) U2.AE26(VSS[153]) U2.AF2(VSS[008]) U2.AF6(VSS[155]) U2.AF8(VSS[156]) U2.AF11(VSS[157]) U2.AF13(VSS[158]) U2.AF16(VSS[159]) U2.AF19(VSS[160]) U2.AF21(VSS[161]) U2.AF25(VSS[163]) U2.B6(VSS[009]) U2.B8(VSS[010]) U2.B11(VSS[011]) U2.B13(VSS[012]) U2.B16(VSS[013]) U2.B19(VSS[014]) U2.B21(VSS[015]) U2.B24(VSS[016]) U2.C2(VSS[023]) U2.C5(VSS[017]) U2.C8(VSS[018]) U2.C11(VSS[019]) U2.C14(VSS[020]) U2.C16(VSS[021]) U2.C19(VSS[022]) U2.C22(VSS[024]) U2.C25(VSS[025]) U2.D1(VSS[026]) U2.D4(VSS[027]) U2.D8(VSS[028]) U2.D11(VSS[029]) U2.D13(VSS[030]) U2.D16(VSS[031]) U2.D19(VSS[032]) U2.D23(VSS[033]) U2.D26(VSS[034]) U2.E3(VSS[035]) U2.E6(VSS[036]) U2.E8(VSS[037]) U2.E11(VSS[038]) U2.E14(VSS[039]) U2.E16(VSS[040]) U2.E19(VSS[041]) U2.E21(VSS[042]) U2.E24(VSS[043]) U2.F2(VSS[050]) U2.F5(VSS[044]) U2.F8(VSS[045]) U2.F11(VSS[046]) U2.F13(VSS[047]) U2.F16(VSS[048]) U2.F19(VSS[049]) U2.F22(VSS[051]) U2.F25(VSS[052]) U2.G1(VSS[054]) U2.G4(VSS[053]) U2.G23(VSS[055]) U2.G26(VSS[056]) U2.H3(VSS[057]) U2.H6(VSS[058]) U2.H21(VSS[059]) U2.H24(VSS[060]) U2.J2(VSS[061]) U2.J5(VSS[062]) U2.J22(VSS[063]) U2.J25(VSS[064]) U2.K1(VSS[065]) U2.K4(VSS[066]) U2.K23(VSS[067]) U2.K26(VSS[068]) U2.L3(VSS[069]) U2.L6(VSS[070]) U2.L21(VSS[071]) U2.L24(VSS[072]) U2.M2(VSS[073]) U2.M5(VSS[074]) U2.M22(VSS[075]) U2.M25(VSS[076]) U2.N1(VSS[077]) U2.N4(VSS[078]) U2.N23(VSS[079]) U2.N26(VSS[080]) U2.P3(VSS[081]) U2.P6(VSS[082]) U2.P21(VSS[083]) U2.P24(VSS[084]) U2.R2(VSS[085]) U2.R5(VSS[086]) U2.R22(VSS[087]) U2.R25(VSS[088]) U2.T1(VSS[089]) U2.T4(VSS[090]) U2.T23(VSS[091]) U2.T26(VSS[092]) U2.U3(VSS[093]) U2.U6(VSS[094]) U2.U21(VSS[095]) U2.U24(VSS[096]) U2.V2(VSS[097]) U2.V5(VSS[098]) U2.V22(VSS[099]) U2.V25(VSS[100]) U2.W1(VSS[101]) U2.W4(VSS[102]) U2.W23(VSS[103]) U2.W26(VSS[104]) U2.Y3(VSS[105]) U2.Y6(VSS[106]) U2.Y21(VSS[107]) U2.Y24(VSS[108]) ; also on sheet 9 10 11 12 13 14 15 16 17 18 19 20 21 22 23 24 25 26 27 28 29 30 31 32 33 34 35 36 37 38 39 40 41
GND_TEMP: U2.B25(THERMDC) ; also on sheet 21
VCC_CORE: C23.1 C24.1 C25.1 C26.1 C27.1 C28.1 C29.1 C30.1 C31.1 C32.1 C33.1 C34.1 C35.1 C36.1 C37.1 C38.1 C39.1 C40.1 C46.1 C47.1 C50.1 C51.1 C52.1 C53.1 R52.2 U2.A7(VCC[001]) U2.A9(VCC[002]) U2.A10(VCC[003]) U2.A12(VCC[004]) U2.A13(VCC[005]) U2.A15(VCC[006]) U2.A17(VCC[007]) U2.A18(VCC[008]) U2.A20(VCC[009]) U2.AA7(VCC[051]) U2.AA9(VCC[052]) U2.AA10(VCC[053]) U2.AA12(VCC[054]) U2.AA13(VCC[055]) U2.AA15(VCC[056]) U2.AA17(VCC[057]) U2.AA18(VCC[058]) U2.AA20(VCC[059]) U2.AB7(VCC[069]) U2.AB9(VCC[060]) U2.AB10(VCC[062]) U2.AB12(VCC[063]) U2.AB14(VCC[064]) U2.AB15(VCC[065]) U2.AB17(VCC[066]) U2.AB18(VCC[067]) U2.AB20(VCC[068]) U2.AC7(VCC[070]) U2.AC9(VCC[071]) U2.AC10(VCC[061]) U2.AC12(VCC[072]) U2.AC13(VCC[073]) U2.AC15(VCC[074]) U2.AC17(VCC[075]) U2.AC18(VCC[076]) U2.AD7(VCC[077]) U2.AD9(VCC[078]) U2.AD10(VCC[079]) U2.AD12(VCC[080]) U2.AD14(VCC[081]) U2.AD15(VCC[082]) U2.AD17(VCC[083]) U2.AD18(VCC[084]) U2.AE9(VCC[085]) U2.AE10(VCC[086]) U2.AE12(VCC[087]) U2.AE13(VCC[088]) U2.AE15(VCC[089]) U2.AE17(VCC[090]) U2.AE18(VCC[091]) U2.AE20(VCC[092]) U2.AF9(VCC[093]) U2.AF10(VCC[094]) U2.AF12(VCC[095]) U2.AF14(VCC[096]) U2.AF15(VCC[097]) U2.AF17(VCC[098]) U2.AF18(VCC[099]) U2.AF20(VCC[100]) U2.B7(VCC[010]) U2.B9(VCC[011]) U2.B10(VCC[012]) U2.B12(VCC[013]) U2.B14(VCC[014]) U2.B15(VCC[015]) U2.B17(VCC[016]) U2.B18(VCC[017]) U2.B20(VCC[018]) U2.C9(VCC[019]) U2.C10(VCC[020]) U2.C12(VCC[021]) U2.C13(VCC[022]) U2.C15(VCC[023]) U2.C17(VCC[024]) U2.C18(VCC[025]) U2.D9(VCC[026]) U2.D10(VCC[027]) U2.D12(VCC[028]) U2.D14(VCC[029]) U2.D15(VCC[030]) U2.D17(VCC[031]) U2.D18(VCC[032]) U2.E7(VCC[033]) U2.E9(VCC[034]) U2.E10(VCC[035]) U2.E12(VCC[036]) U2.E13(VCC[037]) U2.E15(VCC[038]) U2.E17(VCC[039]) U2.E18(VCC[040]) U2.E20(VCC[041]) U2.F7(VCC[042]) U2.F9(VCC[043]) U2.F10(VCC[044]) U2.F12(VCC[045]) U2.F14(VCC[046]) U2.F15(VCC[047]) U2.F17(VCC[048]) U2.F18(VCC[049]) U2.F20(VCC[050]) ; also on sheet 21 31 32
VCC_SENSE: R52.1 U2.AF7(VCCSENSE) ; also on sheet 31
VDD_48: C8.1 C9.1 C10.2 C15.1 C16.2 C20.1 C21.2 FB1.1 U1.1(VDDPCI) U1.7(VDDPCI) U1.11(VDD48) U1.56(VDDREF)
VDD_A: C11.2 C13.1 C14.1 C17.2 C18.1 C19.2 FB2.1 U1.21(VDDPCIEX) U1.28(VDDPCIEX) U1.42(VDDPCIEX) U1.45(VDDA) U1.50(VDDCPU)
VSS_SENSE: R53.2 U2.AE7(VSSSENSE) ; also on sheet 31
14M_ICH: R1.2 ; also on sheet 17
14M_REF: R1.1 U1.60(REF0)
48M_CLK: R3.2 R4.2 R19.2 U1.12(FSLA/USB_48MHz)
CG_XIN: C1.1 U1.58(X1) Y1.2
CG_XOUT: C3.1 U1.57(X2) Y1.1
CGCLK_SMB: Q2.2(SOURCE) R22.1 U1.54(SCLK) ; also on sheet 14 38
CGDAT_SMB: Q1.2(SOURCE) R21.1 U1.55(SDATA) ; also on sheet 14 38
CLK_BSEL0: R4.1 R20.2 R23.1 R24.2
CLK_BSEL1: R25.2 R28.2 R29.1 R30.2 U1.16(FSLB/TEST_MODE)
CLK_BSEL2: R6.1 R31.2 R32.2 R33.1 R34.2
CLK_CPU_BCLK: RP1.2(R2) U2.A22(BCLK[0])
CLK_CPU_BCLK#: RP1.4(R4) U2.A21(BCLK[1])
CLK_DMI_ICH: RP7.4(R4) ; also on sheet 16
CLK_DMI_ICH#: RP7.2(R2) ; also on sheet 16
CLK_MCH_BCLK: RP2.2(R2) U5.AM5(HPLL_CLK)
CLK_MCH_BCLK#: RP2.4(R4) U5.AM7(HPLL_CLK#)
CLK_PCIE_3GPLL: RP3.2(R2) ; also on sheet 9
CLK_PCIE_3GPLL#: RP3.4(R4) ; also on sheet 9
CLK_PCIE_LAN1: RP8.4(R4) ; also on sheet 19
CLK_PCIE_LAN1#: RP8.2(R2) ; also on sheet 19
CLK_PCIE_LAN2: RP9.4(R4) ; also on sheet 20
CLK_PCIE_LAN2#: RP9.2(R2) ; also on sheet 20
CLK_PCIE_LAN3: RP69.4(R4) ; also on sheet 41
CLK_PCIE_LAN3#: RP69.2(R2) ; also on sheet 41
CLK_PWRGD: R2.1 ; also on sheet 17
CLK_SATA: RP6.4(R4) ; also on sheet 15
CLK_SATA#: RP6.2(R2) ; also on sheet 15
CLKGN_REQ3_PCIE: R26.1 U1.32(*PEREQ3#)
CLKGN_REQ4_PCIE: R27.1 U1.33(*PEREQ4#)
CLKLPC2_48: R19.1 ; also on sheet 21
CLKUSB_48: R3.1 ; also on sheet 17
COMP0: R44.1 U2.R26(COMP[0])
COMP1: R46.1 U2.U26(COMP[1])
COMP2: R48.1 U2.AA1(COMP[2])
COMP3: R50.1 U2.Y1(COMP[3])
CPU_BSEL0: R20.1 U2.B22(BSEL[0])
CPU_BSEL1: R28.1 U2.B23(BSEL[1])
CPU_BSEL2: R32.1 U2.C21(BSEL[2])
CPU_DPRSTP#: U2.E5(DPRSTP#) ; also on sheet 9
CPU_GTLREF: R41.1 R51.2 U2.AD26(GTLREF)
DREFCLK: RP11.1(R1) ; also on sheet 9
DREFCLK#: RP11.3(R3) ; also on sheet 9
DREFSSCLK: RP10.4(R4) ; also on sheet 9
DREFSSCLK#: RP10.2(R2) ; also on sheet 9
H_A20M#: U2.A6(A20M#) ; also on sheet 15
H_A#3: U2.J4(A[3]#) U5.J13(H_A#_3)
H_A#4: U2.L5(A[4]#) U5.B11(H_A#_4)
H_A#5: U2.L4(A[5]#) U5.C11(H_A#_5)
H_A#6: U2.K5(A[6]#) U5.M11(H_A#_6)
H_A#7: U2.M3(A[7]#) U5.C15(H_A#_7)
H_A#8: U2.N2(A[8]#) U5.F16(H_A#_8)
H_A#9: U2.J1(A[9]#) U5.L13(H_A#_9)
H_A#10: U2.N3(A[10]#) U5.G17(H_A#_10)
H_A#11: U2.P5(A[11]#) U5.C14(H_A#_11)
H_A#12: U2.P2(A[12]#) U5.K16(H_A#_12)
H_A#13: U2.L2(A[13]#) U5.B13(H_A#_13)
H_A#14: U2.P4(A[14]#) U5.L16(H_A#_14)
H_A#15: U2.P1(A[15]#) U5.J17(H_A#_15)
H_A#16: U2.R1(A[16]#) U5.B14(H_A#_16)
H_A#17: U2.Y2(A[17]#) U5.K19(H_A#_17)
H_A#18: U2.U5(A[18]#) U5.P15(H_A#_18)
H_A#19: U2.R3(A[19]#) U5.R17(H_A#_19)
H_A#20: U2.W6(A[20]#) U5.B16(H_A#_20)
H_A#21: U2.U4(A[21]#) U5.H20(H_A#_21)
H_A#22: U2.Y5(A[22]#) U5.L19(H_A#_22)
H_A#23: U2.U1(A[23]#) U5.D17(H_A#_23)
H_A#24: U2.R4(A[24]#) U5.M17(H_A#_24)
H_A#25: U2.T5(A[25]#) U5.N16(H_A#_25)
H_A#26: U2.T3(A[26]#) U5.J19(H_A#_26)
H_A#27: U2.W2(A[27]#) U5.B18(H_A#_27)
H_A#28: U2.W5(A[28]#) U5.E19(H_A#_28)
H_A#29: U2.Y4(A[29]#) U5.B17(H_A#_29)
H_A#30: U2.U2(A[30]#) U5.B15(H_A#_30)
H_A#31: U2.V4(A[31]#) U5.E17(H_A#_31)
H_A#32: U2.W3(A[32]#) U5.C18(H_A#_32)
H_A#33: U2.AA4(A[33]#) U5.A19(H_A#_33)
H_A#34: U2.AB2(A[34]#) U5.B19(H_A#_34)
H_A#35: U2.AA3(A[35]#) U5.N19(H_A#_35)
H_ADS#: U2.H1(ADS#) U5.G12(H_ADS#)
H_ADSTB0#: U2.M1(ADSTB[0]#) U5.H17(H_ADSTB#_0)
H_ADSTB1#: U2.V1(ADSTB[1]#) U5.G20(H_ADSTB#_1)
H_AVREF: C65.1 R59.1 R60.2 R61.2 U5.B9(H_AVREF)
H_BNR#: U2.E2(BNR#) U5.C8(H_BNR#)
H_BPRI#: U2.G5(BPRI#) U5.E8(H_BPRI#)
H_BREQ#0: U2.F1(BR0#) U5.F12(H_BREQ#)
H_CPURST#: R62.1 U2.C1(RESET#)
H_CPUSLP#: U2.D7(SLP#) U5.E5(H_CPUSLP#)
H_D#0: U2.E22(D[0]#) U5.E2(H_D#_0)
H_D#1: U2.F24(D[1]#) U5.G2(H_D#_1)
H_D#2: U2.E26(D[2]#) U5.G7(H_D#_2)
H_D#3: U2.G22(D[3]#) U5.M6(H_D#_3)
H_D#4: U2.F23(D[4]#) U5.H7(H_D#_4)
H_D#5: U2.G25(D[5]#) U5.H3(H_D#_5)
H_D#6: U2.E25(D[6]#) U5.G4(H_D#_6)
H_D#7: U2.E23(D[7]#) U5.F3(H_D#_7)
H_D#8: U2.K24(D[8]#) U5.N8(H_D#_8)
H_D#9: U2.G24(D[9]#) U5.H2(H_D#_9)
H_D#10: U2.J24(D[10]#) U5.M10(H_D#_10)
H_D#11: U2.J23(D[11]#) U5.N12(H_D#_11)
H_D#12: U2.H22(D[12]#) U5.N9(H_D#_12)
H_D#13: U2.F26(D[13]#) U5.H5(H_D#_13)
H_D#14: U2.K22(D[14]#) U5.P13(H_D#_14)
H_D#15: U2.H23(D[15]#) U5.K9(H_D#_15)
H_D#16: U2.N22(D[16]#) U5.M2(H_D#_16)
H_D#17: U2.K25(D[17]#) U5.W10(H_D#_17)
H_D#18: U2.P26(D[18]#) U5.Y8(H_D#_18)
H_D#19: U2.R23(D[19]#) U5.V4(H_D#_19)
H_D#20: U2.L23(D[20]#) U5.M3(H_D#_20)
H_D#21: U2.M24(D[21]#) U5.J1(H_D#_21)
H_D#22: U2.L22(D[22]#) U5.N5(H_D#_22)
H_D#23: U2.M23(D[23]#) U5.N3(H_D#_23)
H_D#24: U2.P25(D[24]#) U5.W6(H_D#_24)
H_D#25: U2.P23(D[25]#) U5.W9(H_D#_25)
H_D#26: U2.P22(D[26]#) U5.N2(H_D#_26)
H_D#27: U2.T24(D[27]#) U5.Y7(H_D#_27)
H_D#28: U2.R24(D[28]#) U5.Y9(H_D#_28)
H_D#29: U2.L25(D[29]#) U5.P4(H_D#_29)
H_D#30: U2.T25(D[30]#) U5.W3(H_D#_30)
H_D#31: U2.N25(D[31]#) U5.N1(H_D#_31)
H_D#32: U2.Y22(D[32]#) U5.AD12(H_D#_32)
H_D#33: U2.AB24(D[33]#) U5.AE3(H_D#_33)
H_D#34: U2.V24(D[34]#) U5.AD9(H_D#_34)
H_D#35: U2.V26(D[35]#) U5.AC9(H_D#_35)
H_D#36: U2.V23(D[36]#) U5.AC7(H_D#_36)
H_D#37: U2.T22(D[37]#) U5.AC14(H_D#_37)
H_D#38: U2.U25(D[38]#) U5.AD11(H_D#_38)
H_D#39: U2.U23(D[39]#) U5.AC11(H_D#_39)
H_D#40: U2.Y25(D[40]#) U5.AB2(H_D#_40)
H_D#41: U2.W22(D[41]#) U5.AD7(H_D#_41)
H_D#42: U2.Y23(D[42]#) U5.AB1(H_D#_42)
H_D#43: U2.W24(D[43]#) U5.Y3(H_D#_43)
H_D#44: U2.W25(D[44]#) U5.AC6(H_D#_44)
H_D#45: U2.AA23(D[45]#) U5.AE2(H_D#_45)
H_D#46: U2.AA24(D[46]#) U5.AC5(H_D#_46)
H_D#47: U2.AB25(D[47]#) U5.AG3(H_D#_47)
H_D#48: U2.AE24(D[48]#) U5.AJ9(H_D#_48)
H_D#49: U2.AD24(D[49]#) U5.AH8(H_D#_49)
H_D#50: U2.AA21(D[50]#) U5.AJ14(H_D#_50)
H_D#51: U2.AB22(D[51]#) U5.AE9(H_D#_51)
H_D#52: U2.AB21(D[52]#) U5.AE11(H_D#_52)
H_D#53: U2.AC26(D[53]#) U5.AH12(H_D#_53)
H_D#54: U2.AD20(D[54]#) U5.AJ5(H_D#_54)
H_D#55: U2.AE22(D[55]#) U5.AH5(H_D#_55)
H_D#56: U2.AF23(D[56]#) U5.AJ6(H_D#_56)
H_D#57: U2.AC25(D[57]#) U5.AE7(H_D#_57)
H_D#58: U2.AE21(D[58]#) U5.AJ7(H_D#_58)
H_D#59: U2.AD21(D[59]#) U5.AJ2(H_D#_59)
H_D#60: U2.AC22(D[60]#) U5.AE5(H_D#_60)
H_D#61: U2.AD23(D[61]#) U5.AJ3(H_D#_61)
H_D#62: U2.AF22(D[62]#) U5.AH2(H_D#_62)
H_D#63: U2.AC23(D[63]#) U5.AH13(H_D#_63)
H_DBSY#: U2.E1(DBSY#) U5.C10(H_DBSY#)
H_DEFER#: U2.H5(DEFER#) U5.D6(H_DEFER#)
H_DINV#0: U2.H25(DINV[0]#) U5.K5(H_DINV#_0)
H_DINV#1: U2.N24(DINV[1]#) U5.L2(H_DINV#_1)
H_DINV#2: U2.U22(DINV[2]#) U5.AD13(H_DINV#_2)
H_DINV#3: U2.AC20(DINV[3]#) U5.AE13(H_DINV#_3)
H_DPSLP#: U2.B5(DPSLP#) ; also on sheet 15
H_DPWR#: U2.D24(DPWR#) U5.H8(H_DPWR#)
H_DRDY#: U2.F21(DRDY#) U5.K7(H_DRDY#)
H_DSTBN#0: U2.J26(DSTBN[0]#) U5.M7(H_DSTBN#_0)
H_DSTBN#1: U2.L26(DSTBN[1]#) U5.K3(H_DSTBN#_1)
H_DSTBN#2: U2.Y26(DSTBN[2]#) U5.AD2(H_DSTBN#_2)
H_DSTBN#3: U2.AE25(DSTBN[3]#) U5.AH11(H_DSTBN#_3)
H_DSTBP#0: U2.H26(DSTBP[0]#) U5.L7(H_DSTBP#_0)
H_DSTBP#1: U2.M26(DSTBP[1]#) U5.K2(H_DSTBP#_1)
H_DSTBP#2: U2.AA26(DSTBP[2]#) U5.AC2(H_DSTBP#_2)
H_DSTBP#3: U2.AF24(DSTBP[3]#) U5.AJ10(H_DSTBP#_3)
H_DVREF: R60.1 U5.A9(H_DVREF)
H_FERR#: U2.A5(FERR#) ; also on sheet 15
H_HIT#: U2.G6(HIT#) U5.E4(H_HIT#)
H_HITM#: U2.E4(HITM#) U5.C6(H_HITM#)
H_IGNNE#: U2.C4(IGNNE#) ; also on sheet 15
H_INIT#: U2.B3(INIT#) ; also on sheet 15
H_INTR: U2.C6(LINT0) ; also on sheet 15
H_LOCK#: U2.H4(LOCK#) U5.G10(H_LOCK#)
H_NMI: U2.B4(LINT1) ; also on sheet 15
H_PROCHOT_R#: R42.1 U2.D21(PROCHOT#)
H_PWRGD: U2.D6(PWRGOOD) ; also on sheet 15
H_RCOMP: R58.1 U5.C2(H_RCOMP)
H_REQ#0: U2.K3(REQ[0]#) U5.M14(H_REQ#_0)
H_REQ#1: U2.H2(REQ[1]#) U5.E13(H_REQ#_1)
H_REQ#2: U2.K2(REQ[2]#) U5.A11(H_REQ#_2)
H_REQ#3: U2.J3(REQ[3]#) U5.H13(H_REQ#_3)
H_REQ#4: U2.L1(REQ[4]#) U5.B12(H_REQ#_4)
H_RS#0: U2.F3(RS[0]#) U5.E12(H_RS#_0)
H_RS#1: U2.F4(RS[1]#) U5.D7(H_RS#_1)
H_RS#2: U2.G3(RS[2]#) U5.D8(H_RS#_2)
H_SCOMP: R57.1 U5.W1(H_SCOMP)
H_SCOMP#: R56.1 U5.W2(H_SCOMP#)
H_SMI#: U2.A3(SMI#) ; also on sheet 15
H_STPCLK#: R49.1 ; also on sheet 15
H_SWING: C64.1 R54.2 R55.2 U5.B3(H_SWING)
H_THERMDA: U2.A24(THERMDA) ; also on sheet 21
H_TRDY#: U2.G2(TRDY#) U5.B7(H_TRDY#)
LPC_CLK_P80: R12.2 ; also on sheet 24
M_A_A0: U5.BJ19(SA_MA_0) ; also on sheet 14
M_A_A1: U5.BD20(SA_MA_1) ; also on sheet 14
M_A_A2: U5.BK27(SA_MA_2) ; also on sheet 14
M_A_A3: U5.BH28(SA_MA_3) ; also on sheet 14
M_A_A4: U5.BL24(SA_MA_4) ; also on sheet 14
M_A_A5: U5.BK28(SA_MA_5) ; also on sheet 14
M_A_A6: U5.BJ27(SA_MA_6) ; also on sheet 14
M_A_A7: U5.BJ25(SA_MA_7) ; also on sheet 14
M_A_A8: U5.BL28(SA_MA_8) ; also on sheet 14
M_A_A9: U5.BA28(SA_MA_9) ; also on sheet 14
M_A_A10: U5.BC19(SA_MA_10) ; also on sheet 14
M_A_A11: U5.BE28(SA_MA_11) ; also on sheet 14
M_A_A12: U5.BG30(SA_MA_12) ; also on sheet 14
M_A_A13: U5.BJ16(SA_MA_13) ; also on sheet 14
M_A_BS#0: U5.BB19(SA_BS_0) ; also on sheet 14
M_A_BS#1: U5.BK19(SA_BS_1) ; also on sheet 14
M_A_BS#2: U5.BF29(SA_BS_2) ; also on sheet 14
M_A_CAS#: U5.BL17(SA_CAS#) ; also on sheet 14
M_A_DM0: U5.AT45(SA_DM_0) ; also on sheet 14
M_A_DM1: U5.BD44(SA_DM_1) ; also on sheet 14
M_A_DM2: U5.BD42(SA_DM_2) ; also on sheet 14
M_A_DM3: U5.AW38(SA_DM_3) ; also on sheet 14
M_A_DM4: U5.AW13(SA_DM_4) ; also on sheet 14
M_A_DM5: U5.BG8(SA_DM_5) ; also on sheet 14
M_A_DM6: U5.AY5(SA_DM_6) ; also on sheet 14
M_A_DM7: U5.AN6(SA_DM_7) ; also on sheet 14
M_A_DQ0: U5.AR43(SA_DQ_0) ; also on sheet 14
M_A_DQ1: U5.AW44(SA_DQ_1) ; also on sheet 14
M_A_DQ2: U5.BA45(SA_DQ_2) ; also on sheet 14
M_A_DQ3: U5.AY46(SA_DQ_3) ; also on sheet 14
M_A_DQ4: U5.AR41(SA_DQ_4) ; also on sheet 14
M_A_DQ5: U5.AR45(SA_DQ_5) ; also on sheet 14
M_A_DQ6: U5.AT42(SA_DQ_6) ; also on sheet 14
M_A_DQ7: U5.AW47(SA_DQ_7) ; also on sheet 14
M_A_DQ8: U5.BB45(SA_DQ_8) ; also on sheet 14
M_A_DQ9: U5.BF48(SA_DQ_9) ; also on sheet 14
M_A_DQ10: U5.BG47(SA_DQ_10) ; also on sheet 14
M_A_DQ11: U5.BJ45(SA_DQ_11) ; also on sheet 14
M_A_DQ12: U5.BB47(SA_DQ_12) ; also on sheet 14
M_A_DQ13: U5.BG50(SA_DQ_13) ; also on sheet 14
M_A_DQ14: U5.BH49(SA_DQ_14) ; also on sheet 14
M_A_DQ15: U5.BE45(SA_DQ_15) ; also on sheet 14
M_A_DQ16: U5.AW43(SA_DQ_16) ; also on sheet 14
M_A_DQ17: U5.BE44(SA_DQ_17) ; also on sheet 14
M_A_DQ18: U5.BG42(SA_DQ_18) ; also on sheet 14
M_A_DQ19: U5.BE40(SA_DQ_19) ; also on sheet 14
M_A_DQ20: U5.BF44(SA_DQ_20) ; also on sheet 14
M_A_DQ21: U5.BH45(SA_DQ_21) ; also on sheet 14
M_A_DQ22: U5.BG40(SA_DQ_22) ; also on sheet 14
M_A_DQ23: U5.BF40(SA_DQ_23) ; also on sheet 14
M_A_DQ24: U5.AR40(SA_DQ_24) ; also on sheet 14
M_A_DQ25: U5.AW40(SA_DQ_25) ; also on sheet 14
M_A_DQ26: U5.AT39(SA_DQ_26) ; also on sheet 14
M_A_DQ27: U5.AW36(SA_DQ_27) ; also on sheet 14
M_A_DQ28: U5.AW41(SA_DQ_28) ; also on sheet 14
M_A_DQ29: U5.AY41(SA_DQ_29) ; also on sheet 14
M_A_DQ30: U5.AV38(SA_DQ_30) ; also on sheet 14
M_A_DQ31: U5.AT38(SA_DQ_31) ; also on sheet 14
M_A_DQ32: U5.AV13(SA_DQ_32) ; also on sheet 14
M_A_DQ33: U5.AT13(SA_DQ_33) ; also on sheet 14
M_A_DQ34: U5.AW11(SA_DQ_34) ; also on sheet 14
M_A_DQ35: U5.AV11(SA_DQ_35) ; also on sheet 14
M_A_DQ36: U5.AU15(SA_DQ_36) ; also on sheet 14
M_A_DQ37: U5.AT11(SA_DQ_37) ; also on sheet 14
M_A_DQ38: U5.BA13(SA_DQ_38) ; also on sheet 14
M_A_DQ39: U5.BA11(SA_DQ_39) ; also on sheet 14
M_A_DQ40: U5.BE10(SA_DQ_40) ; also on sheet 14
M_A_DQ41: U5.BD10(SA_DQ_41) ; also on sheet 14
M_A_DQ42: U5.BD8(SA_DQ_42) ; also on sheet 14
M_A_DQ43: U5.AY9(SA_DQ_43) ; also on sheet 14
M_A_DQ44: U5.BG10(SA_DQ_44) ; also on sheet 14
M_A_DQ45: U5.AW9(SA_DQ_45) ; also on sheet 14
M_A_DQ46: U5.BD7(SA_DQ_46) ; also on sheet 14
M_A_DQ47: U5.BB9(SA_DQ_47) ; also on sheet 14
M_A_DQ48: U5.BB5(SA_DQ_48) ; also on sheet 14
M_A_DQ49: U5.AY7(SA_DQ_49) ; also on sheet 14
M_A_DQ50: U5.AT5(SA_DQ_50) ; also on sheet 14
M_A_DQ51: U5.AT7(SA_DQ_51) ; also on sheet 14
M_A_DQ52: U5.AY6(SA_DQ_52) ; also on sheet 14
M_A_DQ53: U5.BB7(SA_DQ_53) ; also on sheet 14
M_A_DQ54: U5.AR5(SA_DQ_54) ; also on sheet 14
M_A_DQ55: U5.AR8(SA_DQ_55) ; also on sheet 14
M_A_DQ56: U5.AR9(SA_DQ_56) ; also on sheet 14
M_A_DQ57: U5.AN3(SA_DQ_57) ; also on sheet 14
M_A_DQ58: U5.AM8(SA_DQ_58) ; also on sheet 14
M_A_DQ59: U5.AN10(SA_DQ_59) ; also on sheet 14
M_A_DQ60: U5.AT9(SA_DQ_60) ; also on sheet 14
M_A_DQ61: U5.AN9(SA_DQ_61) ; also on sheet 14
M_A_DQ62: U5.AM9(SA_DQ_62) ; also on sheet 14
M_A_DQ63: U5.AN11(SA_DQ_63) ; also on sheet 14
M_A_DQS0: U5.AT46(SA_DQS_0) ; also on sheet 14
M_A_DQS1: U5.BE48(SA_DQS_1) ; also on sheet 14
M_A_DQS2: U5.BB43(SA_DQS_2) ; also on sheet 14
M_A_DQS3: U5.BC37(SA_DQS_3) ; also on sheet 14
M_A_DQS4: U5.BB16(SA_DQS_4) ; also on sheet 14
M_A_DQS5: U5.BH6(SA_DQS_5) ; also on sheet 14
M_A_DQS6: U5.BB2(SA_DQS_6) ; also on sheet 14
M_A_DQS7: U5.AP3(SA_DQS_7) ; also on sheet 14
M_A_DQS#0: U5.AT47(SA_DQS#_0) ; also on sheet 14
M_A_DQS#1: U5.BD47(SA_DQS#_1) ; also on sheet 14
M_A_DQS#2: U5.BC41(SA_DQS#_2) ; also on sheet 14
M_A_DQS#3: U5.BA37(SA_DQS#_3) ; also on sheet 14
M_A_DQS#4: U5.BA16(SA_DQS#_4) ; also on sheet 14
M_A_DQS#5: U5.BH7(SA_DQS#_5) ; also on sheet 14
M_A_DQS#6: U5.BC1(SA_DQS#_6) ; also on sheet 14
M_A_DQS#7: U5.AP2(SA_DQS#_7) ; also on sheet 14
M_A_RAS#: U5.BE18(SA_RAS#) ; also on sheet 14
M_A_WE#: U5.BA19(SA_WE#) ; also on sheet 14
M_B_A0: U5.BC18(SB_MA_0) ; also on sheet 37
M_B_A1: U5.BG28(SB_MA_1) ; also on sheet 37
M_B_A2: U5.BG25(SB_MA_2) ; also on sheet 37
M_B_A3: U5.AW17(SB_MA_3) ; also on sheet 37
M_B_A4: U5.BF25(SB_MA_4) ; also on sheet 37
M_B_A5: U5.BE25(SB_MA_5) ; also on sheet 37
M_B_A6: U5.BA29(SB_MA_6) ; also on sheet 37
M_B_A7: U5.BC28(SB_MA_7) ; also on sheet 37
M_B_A8: U5.AY28(SB_MA_8) ; also on sheet 37
M_B_A9: U5.BD37(SB_MA_9) ; also on sheet 37
M_B_A10: U5.BG17(SB_MA_10) ; also on sheet 37
M_B_A11: U5.BE37(SB_MA_11) ; also on sheet 37
M_B_A12: U5.BA39(SB_MA_12) ; also on sheet 37
M_B_A13: U5.BG13(SB_MA_13) ; also on sheet 37
M_B_BS#0: U5.AY17(SB_BS_0) ; also on sheet 37
M_B_BS#1: U5.BG18(SB_BS_1) ; also on sheet 37
M_B_BS#2: U5.BG36(SB_BS_2) ; also on sheet 37
M_B_CAS#: U5.BE17(SB_CAS#) ; also on sheet 37
M_B_DM0: U5.AR50(SB_DM_0) ; also on sheet 38
M_B_DM1: U5.BD49(SB_DM_1) ; also on sheet 38
M_B_DM2: U5.BK45(SB_DM_2) ; also on sheet 38
M_B_DM3: U5.BL39(SB_DM_3) ; also on sheet 38
M_B_DM4: U5.BH12(SB_DM_4) ; also on sheet 38
M_B_DM5: U5.BJ7(SB_DM_5) ; also on sheet 38
M_B_DM6: U5.BF3(SB_DM_6) ; also on sheet 38
M_B_DM7: U5.AW2(SB_DM_7) ; also on sheet 38
M_B_DQ0: U5.AP49(SB_DQ_0) ; also on sheet 37
M_B_DQ1: U5.AR51(SB_DQ_1) ; also on sheet 37
M_B_DQ2: U5.AW50(SB_DQ_2) ; also on sheet 37
M_B_DQ3: U5.AW51(SB_DQ_3) ; also on sheet 37
M_B_DQ4: U5.AN51(SB_DQ_4) ; also on sheet 37
M_B_DQ5: U5.AN50(SB_DQ_5) ; also on sheet 37
M_B_DQ6: U5.AV50(SB_DQ_6) ; also on sheet 37
M_B_DQ7: U5.AV49(SB_DQ_7) ; also on sheet 37
M_B_DQ8: U5.BA50(SB_DQ_8) ; also on sheet 37
M_B_DQ9: U5.BB50(SB_DQ_9) ; also on sheet 37
M_B_DQ10: U5.BA49(SB_DQ_10) ; also on sheet 37
M_B_DQ11: U5.BE50(SB_DQ_11) ; also on sheet 37
M_B_DQ12: U5.BA51(SB_DQ_12) ; also on sheet 37
M_B_DQ13: U5.AY49(SB_DQ_13) ; also on sheet 37
M_B_DQ14: U5.BF50(SB_DQ_14) ; also on sheet 37
M_B_DQ15: U5.BF49(SB_DQ_15) ; also on sheet 37
M_B_DQ16: U5.BJ50(SB_DQ_16) ; also on sheet 37
M_B_DQ17: U5.BJ44(SB_DQ_17) ; also on sheet 37
M_B_DQ18: U5.BJ43(SB_DQ_18) ; also on sheet 37
M_B_DQ19: U5.BL43(SB_DQ_19) ; also on sheet 37
M_B_DQ20: U5.BK47(SB_DQ_20) ; also on sheet 37
M_B_DQ21: U5.BK49(SB_DQ_21) ; also on sheet 37
M_B_DQ22: U5.BK43(SB_DQ_22) ; also on sheet 37
M_B_DQ23: U5.BK42(SB_DQ_23) ; also on sheet 37
M_B_DQ24: U5.BJ41(SB_DQ_24) ; also on sheet 37
M_B_DQ25: U5.BL41(SB_DQ_25) ; also on sheet 37
M_B_DQ26: U5.BJ37(SB_DQ_26) ; also on sheet 37
M_B_DQ27: U5.BJ36(SB_DQ_27) ; also on sheet 37
M_B_DQ28: U5.BK41(SB_DQ_28) ; also on sheet 37
M_B_DQ29: U5.BJ40(SB_DQ_29) ; also on sheet 37
M_B_DQ30: U5.BL35(SB_DQ_30) ; also on sheet 37
M_B_DQ31: U5.BK37(SB_DQ_31) ; also on sheet 37
M_B_DQ32: U5.BK13(SB_DQ_32) ; also on sheet 37
M_B_DQ33: U5.BE11(SB_DQ_33) ; also on sheet 37
M_B_DQ34: U5.BK11(SB_DQ_34) ; also on sheet 37
M_B_DQ35: U5.BC11(SB_DQ_35) ; also on sheet 37
M_B_DQ36: U5.BC13(SB_DQ_36) ; also on sheet 37
M_B_DQ37: U5.BE12(SB_DQ_37) ; also on sheet 37
M_B_DQ38: U5.BC12(SB_DQ_38) ; also on sheet 37
M_B_DQ39: U5.BG12(SB_DQ_39) ; also on sheet 37
M_B_DQ40: U5.BJ10(SB_DQ_40) ; also on sheet 37
M_B_DQ41: U5.BL9(SB_DQ_41) ; also on sheet 37
M_B_DQ42: U5.BK5(SB_DQ_42) ; also on sheet 37
M_B_DQ43: U5.BL5(SB_DQ_43) ; also on sheet 37
M_B_DQ44: U5.BK9(SB_DQ_44) ; also on sheet 37
M_B_DQ45: U5.BK10(SB_DQ_45) ; also on sheet 37
M_B_DQ46: U5.BJ8(SB_DQ_46) ; also on sheet 37
M_B_DQ47: U5.BJ6(SB_DQ_47) ; also on sheet 37
M_B_DQ48: U5.BF4(SB_DQ_48) ; also on sheet 37
M_B_DQ49: U5.BH5(SB_DQ_49) ; also on sheet 37
M_B_DQ50: U5.BG1(SB_DQ_50) ; also on sheet 37
M_B_DQ51: U5.BC2(SB_DQ_51) ; also on sheet 37
M_B_DQ52: U5.BK3(SB_DQ_52) ; also on sheet 37
M_B_DQ53: U5.BE4(SB_DQ_53) ; also on sheet 37
M_B_DQ54: U5.BD3(SB_DQ_54) ; also on sheet 37
M_B_DQ55: U5.BJ2(SB_DQ_55) ; also on sheet 37
M_B_DQ56: U5.BA3(SB_DQ_56) ; also on sheet 37
M_B_DQ57: U5.BB3(SB_DQ_57) ; also on sheet 37
M_B_DQ58: U5.AR1(SB_DQ_58) ; also on sheet 37
M_B_DQ59: U5.AT3(SB_DQ_59) ; also on sheet 37
M_B_DQ60: U5.AY2(SB_DQ_60) ; also on sheet 37
M_B_DQ61: U5.AY3(SB_DQ_61) ; also on sheet 37
M_B_DQ62: U5.AU2(SB_DQ_62) ; also on sheet 37
M_B_DQ63: U5.AT2(SB_DQ_63) ; also on sheet 37
M_B_DQS0: U5.AT50(SB_DQS_0) ; also on sheet 38
M_B_DQS1: U5.BD50(SB_DQS_1) ; also on sheet 38
M_B_DQS2: U5.BK46(SB_DQS_2) ; also on sheet 38
M_B_DQS3: U5.BK39(SB_DQS_3) ; also on sheet 38
M_B_DQS4: U5.BJ12(SB_DQS_4) ; also on sheet 38
M_B_DQS5: U5.BL7(SB_DQS_5) ; also on sheet 38
M_B_DQS6: U5.BE2(SB_DQS_6) ; also on sheet 38
M_B_DQS7: U5.AV2(SB_DQS_7) ; also on sheet 38
M_B_DQS#0: U5.AU50(SB_DQS#_0) ; also on sheet 38
M_B_DQS#1: U5.BC50(SB_DQS#_1) ; also on sheet 38
M_B_DQS#2: U5.BL45(SB_DQS#_2) ; also on sheet 38
M_B_DQS#3: U5.BK38(SB_DQS#_3) ; also on sheet 38
M_B_DQS#4: U5.BK12(SB_DQS#_4) ; also on sheet 38
M_B_DQS#5: U5.BK7(SB_DQS#_5) ; also on sheet 38
M_B_DQS#6: U5.BF2(SB_DQS#_6) ; also on sheet 38
M_B_DQS#7: U5.AV3(SB_DQS#_7) ; also on sheet 38
M_B_RAS#: U5.AV16(SB_RAS#) ; also on sheet 37
M_B_WE#: U5.BC17(SB_WE#) ; also on sheet 37
MCH_BSEL0: R23.2 ; also on sheet 9
MCH_BSEL1: R29.2 ; also on sheet 9
MCH_BSEL2: R33.2 ; also on sheet 9
PCI_CLK_SLOTS: R11.2 ; also on sheet 27
PCLK_ICH: R15.2 ; also on sheet 16
PCLK_LPC2: R9.2 ; also on sheet 21
PCLK_SMB: Q2.3(DRAIN) ; also on sheet 17 28
PDAT_SMB: Q1.3(DRAIN) ; also on sheet 17 28
PM_STPCPU#: U1.62(CPU_STOP#) ; also on sheet 17
PM_STPPCI#: U1.63(PCI/PCIeX_STOP#) ; also on sheet 17
PM_THRMTRIP#: R43.2 ; also on sheet 9 15
PSI#: U2.AE6(PSI#) ; also on sheet 31
R_CLK_PCIE_LAN1: RP8.3(R3) U1.22(PCIeXT_L2)
R_CLK_PCIE_LAN1#: RP8.1(R1) U1.23(PCIeXC_L2)
R_CLK_PCIE_LAN2: RP9.3(R3) U1.19(PCIeXT_L1)
R_CLK_PCIE_LAN2#: RP9.1(R1) U1.20(PCIeXC_L1)
R_CLK_SATA: RP6.3(R3) U1.26(SATACLKT_L)
R_CLK_SATA#: RP6.1(R1) U1.27(SATACLKC_L)
R_DOT96: RP11.2(R2) U1.14(PCIeT_L9/DOTT_96MHzL)
R_DOT96#: RP11.4(R4) U1.15(PCIeC_L9/DOTC_96MHzL)
R_DREFSSCLK: RP10.3(R3) U1.17(27FIX/LCD_SSCGT/PCIeXT_L0)
R_DREFSSCLK#: RP10.1(R1) U1.18(27SS/LCD_SSCGC/PCIeXC_L0)
R_PCLK_ICH: R15.1 R18.2 U1.8(ITPEN/PCICLK_F4)
R_PCLK_SIO: R9.1 U1.3(PCICLK1)
R_PCLK_SLOT: R11.1 R17.1 U1.9(*SELLCD_27#/PCICLK_F5)
RHCLK_CPU: RP1.1(R1) U1.52(CPUT_L0)
RHCLK_CPU#: RP1.3(R3) U1.51(CPUC_L0)
RHCLK_MCH: RP2.1(R1) U1.49(CPUT_L1F)
RHCLK_MCH#: RP2.3(R3) U1.48(CPUC_L1F)
RSRC_ICH: RP7.3(R3) U1.24(PCIeXT_L3)
RSRC_ICH#: RP7.1(R1) U1.25(PCIeXC_L3)
RSRC_MCH: RP3.1(R1) U1.39(PCIeXT_L6)
RSRC_MCH#: RP3.3(R3) U1.38(PCIeXC_L6)
SYS_RST#: R378.1 ; also on sheet 17 25 26
TP_MB_RCVEN#: T14.1 U5.AY18(SB_RCVEN#)
VID0: U2.AD6(VID[0]) ; also on sheet 31
VID1: U2.AF5(VID[1]) ; also on sheet 31
VID2: U2.AE5(VID[2]) ; also on sheet 31
VID3: U2.AF4(VID[3]) ; also on sheet 31
VID4: U2.AE3(VID[4]) ; also on sheet 31
VID5: U2.AF3(VID[5]) ; also on sheet 31
VID6: U2.AE2(VID[6]) ; also on sheet 31
VREF: R7.2 R8.2 U1.47(VREF)
XDP_BPM#5: R38.1 U2.AC1(PREQ#)
XDP_DBRESET#: R378.2 U2.C20(DBR#)
XDP_TCK: R39.1 U2.AC5(TCK)
XDP_TDI: R37.1 U2.AA6(TDI)
XDP_TMS: R36.1 U2.AB5(TMS)
XDP_TRST#: R40.1 U2.AB6(TRST#)
N52477248: R62.2 U5.B6(H_CPURST#)
N62505937: R6.2 U1.61(REF1/FSLC/TEST_SEL)
N62506000: R12.1 R16.1 U1.64(**PCICLK0/REQ_SEL)
N62506723: R2.2 U1.10(Vtt_PWRGD/PD#)
N79245086: R43.1 U2.C7(THERMTRIP#)
N79245162: R35.1 U2.D20(IERR#)
N91565150: R49.2 U2.D5(STPCLK#)
N115843872: RP69.3(R3) U1.30(PCIeXT_L4)
N115847550: RP69.1(R1) U1.31(PCIeXC_L4)

Not connected (* = marked no-connect by the designer): U1 4(PCICL2)* 5(*SELPCIeX0_LCD#/PCICLK3)* 34(*PWRSAVE#)* 35(PCIeXC_L5)* 36(PCIeXT_L5)* 40(PEREQ2#PCIeXCT_L7)* 41(PREQ1#PCIeXT_L7)* 43(CPUITPC_L2/PCIeXC_L8)* 44(CPUITPT_L2/PCIeXT_L8)*; U2 A26(TEST6)* AB3(TDO)* AC2(PRDY#)* AC4(BPM[3]#)* AD1(BPM[2]#)* AD3(BPM[1]#)* AD4(BPM[0]#)* AF1(TEST5)* AF26(TEST4)* B2(RSVD[05])* C3(RSVD[06])* C23(TEST1)* C24(TEST3)* D2(RSVD[07])* D3(RSVD[09])* D22(RSVD[08])* D25(TEST2)* F6(RSVD[10])* M4(RSVD[01])* N5(RSVD[02])* T2(RSVD[03])* V3(RSVD[04])*; U5 AY20(SA_RCVEN#)*

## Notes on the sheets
sheet 1
- CPCI965 R0A
- 01--COVER PAGE
- 19--GIGA LAN1
- 02--BLOCK DIAGRAM
- 20--GIGA LAN2
- 03--CLOCK &DEVICE TABLE
- 21--82559 PCI LAN
- 04--CLOCK GENERATOR
- 22--CODAC ALC888
- 05--CPU (1 of 2)
- 23--CF slot
- 06--CPU (2 of 2)
- 24--SIO_W83627THF
- 07--GMCH HOST (1 of 7)
- 25--TPM & COM
- 08--GMCH DDR (2 of 7)
- 26--VGA swtich&PIO
- 09--GMCH DMI & STRAP (3 of 7)
- 27--J1 PCI32&BRIDGE
- 10--GMCH VGA (4 of 7)
- 28--J2 J3 PCIE
- 11--GMCH POWER 1 (5 of 7)
- 29--J4 HDD&LVDS&AUDIO
- 12--GMCH POWER 2 (6 of 7)
- 30--J5 VGA&USB&ETC
- 13--GMCH GND (7 of 7)
- 31--ISL6262A(VCORE)
- 14--SO-DIMM & TERMINATOR
- 32--ISL6520A(MCH&ICH)
- 15--ICH8-M HOST (1 of 4),3*SATA
- 33--TPS51116(MEMORY)
- 16--ICH8-M PCI E(2 of 4)
- 34--CPCI HOT SWAP & MTG
- 17--ICH8-M GPIO (3 of 4)
- 35--POWER BLOCK
- 18--ICH8-M Power (4 of 4)
sheet 2
- RS232
- LAN3
- USB*2
- LAN1
- LAN2
- VGA
- SWTICH
- SIO
  W83627
- TPM
- CF
   SLOT
- SWTICH
- SWTICH
- SODIMM
- ON BD
- 82573L
- 82573L
- 533/667
- 533/667
- MHZ
- MHZ
- LPC BUS
- USB
- IDE
- PCIEX1
- PCIEX1
- DDR2 CHA
- DDR2 CHB
- NIC
  82559 *2
- LPC
- Merom
- ICH8-M
- DMI
- DMI
- CRESTLINE-GM
- FSB
- FSB 667 MHz
  (166 x 4)
- FSB
- INTEL
   Mobile479  CPU
- PCI
- PCI BUS
- PCIEX1 *4
- SATA
- AUDIO
- PEG/SDVO *2
- LVDS
- VGA
- PCI BRIDGE
- ALC888
- SWTICH
- PCI 32
- PCI 32 EXT *8
- PCIE X1  *4
- PEG/SDVO *2
- IDE
- IDE
- SATA*2
- SATA*2
- AUDIO
- AUDIO
- LVDS
- LVDS
- LAN1
- LAN1
- LAN2
- USB*4
- PS2
- RS422
- RS232
- VGA
- LPT
- J2
- J1
- J3
- J4
- J5
sheet 3
- CLK_CPU_BCLK/200Mhz
- Merom
- CLK_MCH_BCLK/133Mhz
- M_CLK_DDR0/133Mhz
- M_CLK_DDR1/133Mhz
- CLK_PCIE_3GPLL/100Mhz
- FSB
- DDR2 I/F
- SO-DIMM
  ChA
- PCI-E
- GMCH
- DREFSSCLK/100Mhz
- M_CLK_DDR2/133Mhz
- SO-DIMM
  ChB
- DREFCLK/100Mhz
- M_CLK_DDR3/133Mhz
- CLK_PCIE_ICH/100Mhz
- PCI-E
- 32.768KHz
- CK505
- CLK_SATA/100Mhz
- CLKUSB_48/48Mhz
- SATA
- ICH8-M
- USB
- 14M_ICH/14Mhz
- RTC
- PCLK_ICH/33Mhz
- PCI
- PCI_CLK_SLOTS/33Mhz
- CLK_J2_PE/100Mhz
- CLK BUF
- S_CLK0/33Mhz
- CLK_J2_PE0/100Mhz
- CPCI J1
- S_CLK[1:8]/33Mhz
- PCI BRIGDE
- CLK_J2_PE1/100Mhz
- CLK_J2_PE2/100Mhz
- CPCI J2
- CLK_J2_PE3/100Mhz
- CLK_PEX16/100Mhz
- CPCI J3
- CLK_PCIE_LAN1/100Mhz
- LAN1 88E8055
- 25MHz
- CLK_PCIE_LAN2/100Mhz
- LAN2 88E8055
- 25MHz
- PCI_CLK_LAN/33Mhz
- LAN3 82559
- 25MHz
- LPC_CLK_TPM/33Mhz
- TPM SLB9635TT1.2
- 32.768KHz
- PCLK_LPC/33Mhz
- SIO
  W83627
- CLKLPC_48/48Mhz
- 14.318MHz
- PCI DEVICE TABLE
- 82559 LAN
- REQ 0
- GNT 0
- AD17
- INTA
- PCI_CLK_LAN
- PCI BRIDGE
- REQ 1
- GNT 1
- AD18
- TBD
- PCI_CLK_SLOTS
sheet 4
- Place these termination to close CK505.
- FSC   FSB   FSA     CPU       SRC        PCI
- 1        0        1          100        100          33
- 0        0        1          133        100          33
- 0        1        1          166        100          33
- Default
- 0        1        0          200        100          33
- 0        0        0          266        100          33
- 1        0        0          333        100          33
- Change to 2.2K and 10K
  nicole 7/24
- 1        1        0          400        100          33
- 1        1        1          200        100          33
- LATCH SELECT TABLE
- Pin5
- Pin9
- Pin14/15
- Pin17/18
- 0
- 0
- PCIEX9
- 27MHz
- 0
- 1
- PCIEX9
- LCD
- *
- 1
- x
- DOT96
- PCIEX0
- Pin64
- Pin8
- Zo=50
- 0
- PCIEXCLK
- *
- 0
- SRC Pair
- *
- 1
- PEREQ#
- 1
- CPUITP Pair
- *  Internal pull up to VDD
  **Internal pull down to GND
- ITP/SRC7 SELECT
  0: SRC7  1: ITP
- For clock gen. and DIMM are powered
  by +V3.3M, per intel
  nicole, 7/27
- 010  200MHz
- REQ3 Latched Select
  "0" : CLK Control Enable
  "1" : CLK Control
  Disable : PCIE 2,4
- REQ4 Latched Select
  "0" : CLK Control Enable
  "1" : CLK Control  Disable : PCIE 3,5,7
- 25 mils
- 400mA
- 25 mils
sheet 5
- Layout Note:
  Width of GTLREF
  is 5mil,
  Place voltage
  divider
  within 0.5" of
  GTLREF pin.
- H_PWRGD is CMOS driving by ICH
- TO VRD
sheet 6
- LV 23A
- 4.5A(LV)
- 120mA(LV)
- Near CPU <1inch, 18/50mils
  nicole
sheet 7
- 10/20mil
- <500mil from GMCH pins
- <500mil from GMCH pins
